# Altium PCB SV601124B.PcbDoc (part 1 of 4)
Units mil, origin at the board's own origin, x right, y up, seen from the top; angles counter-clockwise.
Board outline 3733 x 2734 mil, 4 copper layers (Top Layer, Mid-Layer 1, Mid-Layer 2, Bottom Layer), stack 60.2 mil thick; 246 components, 169 nets, 780 pads, 426 vias.
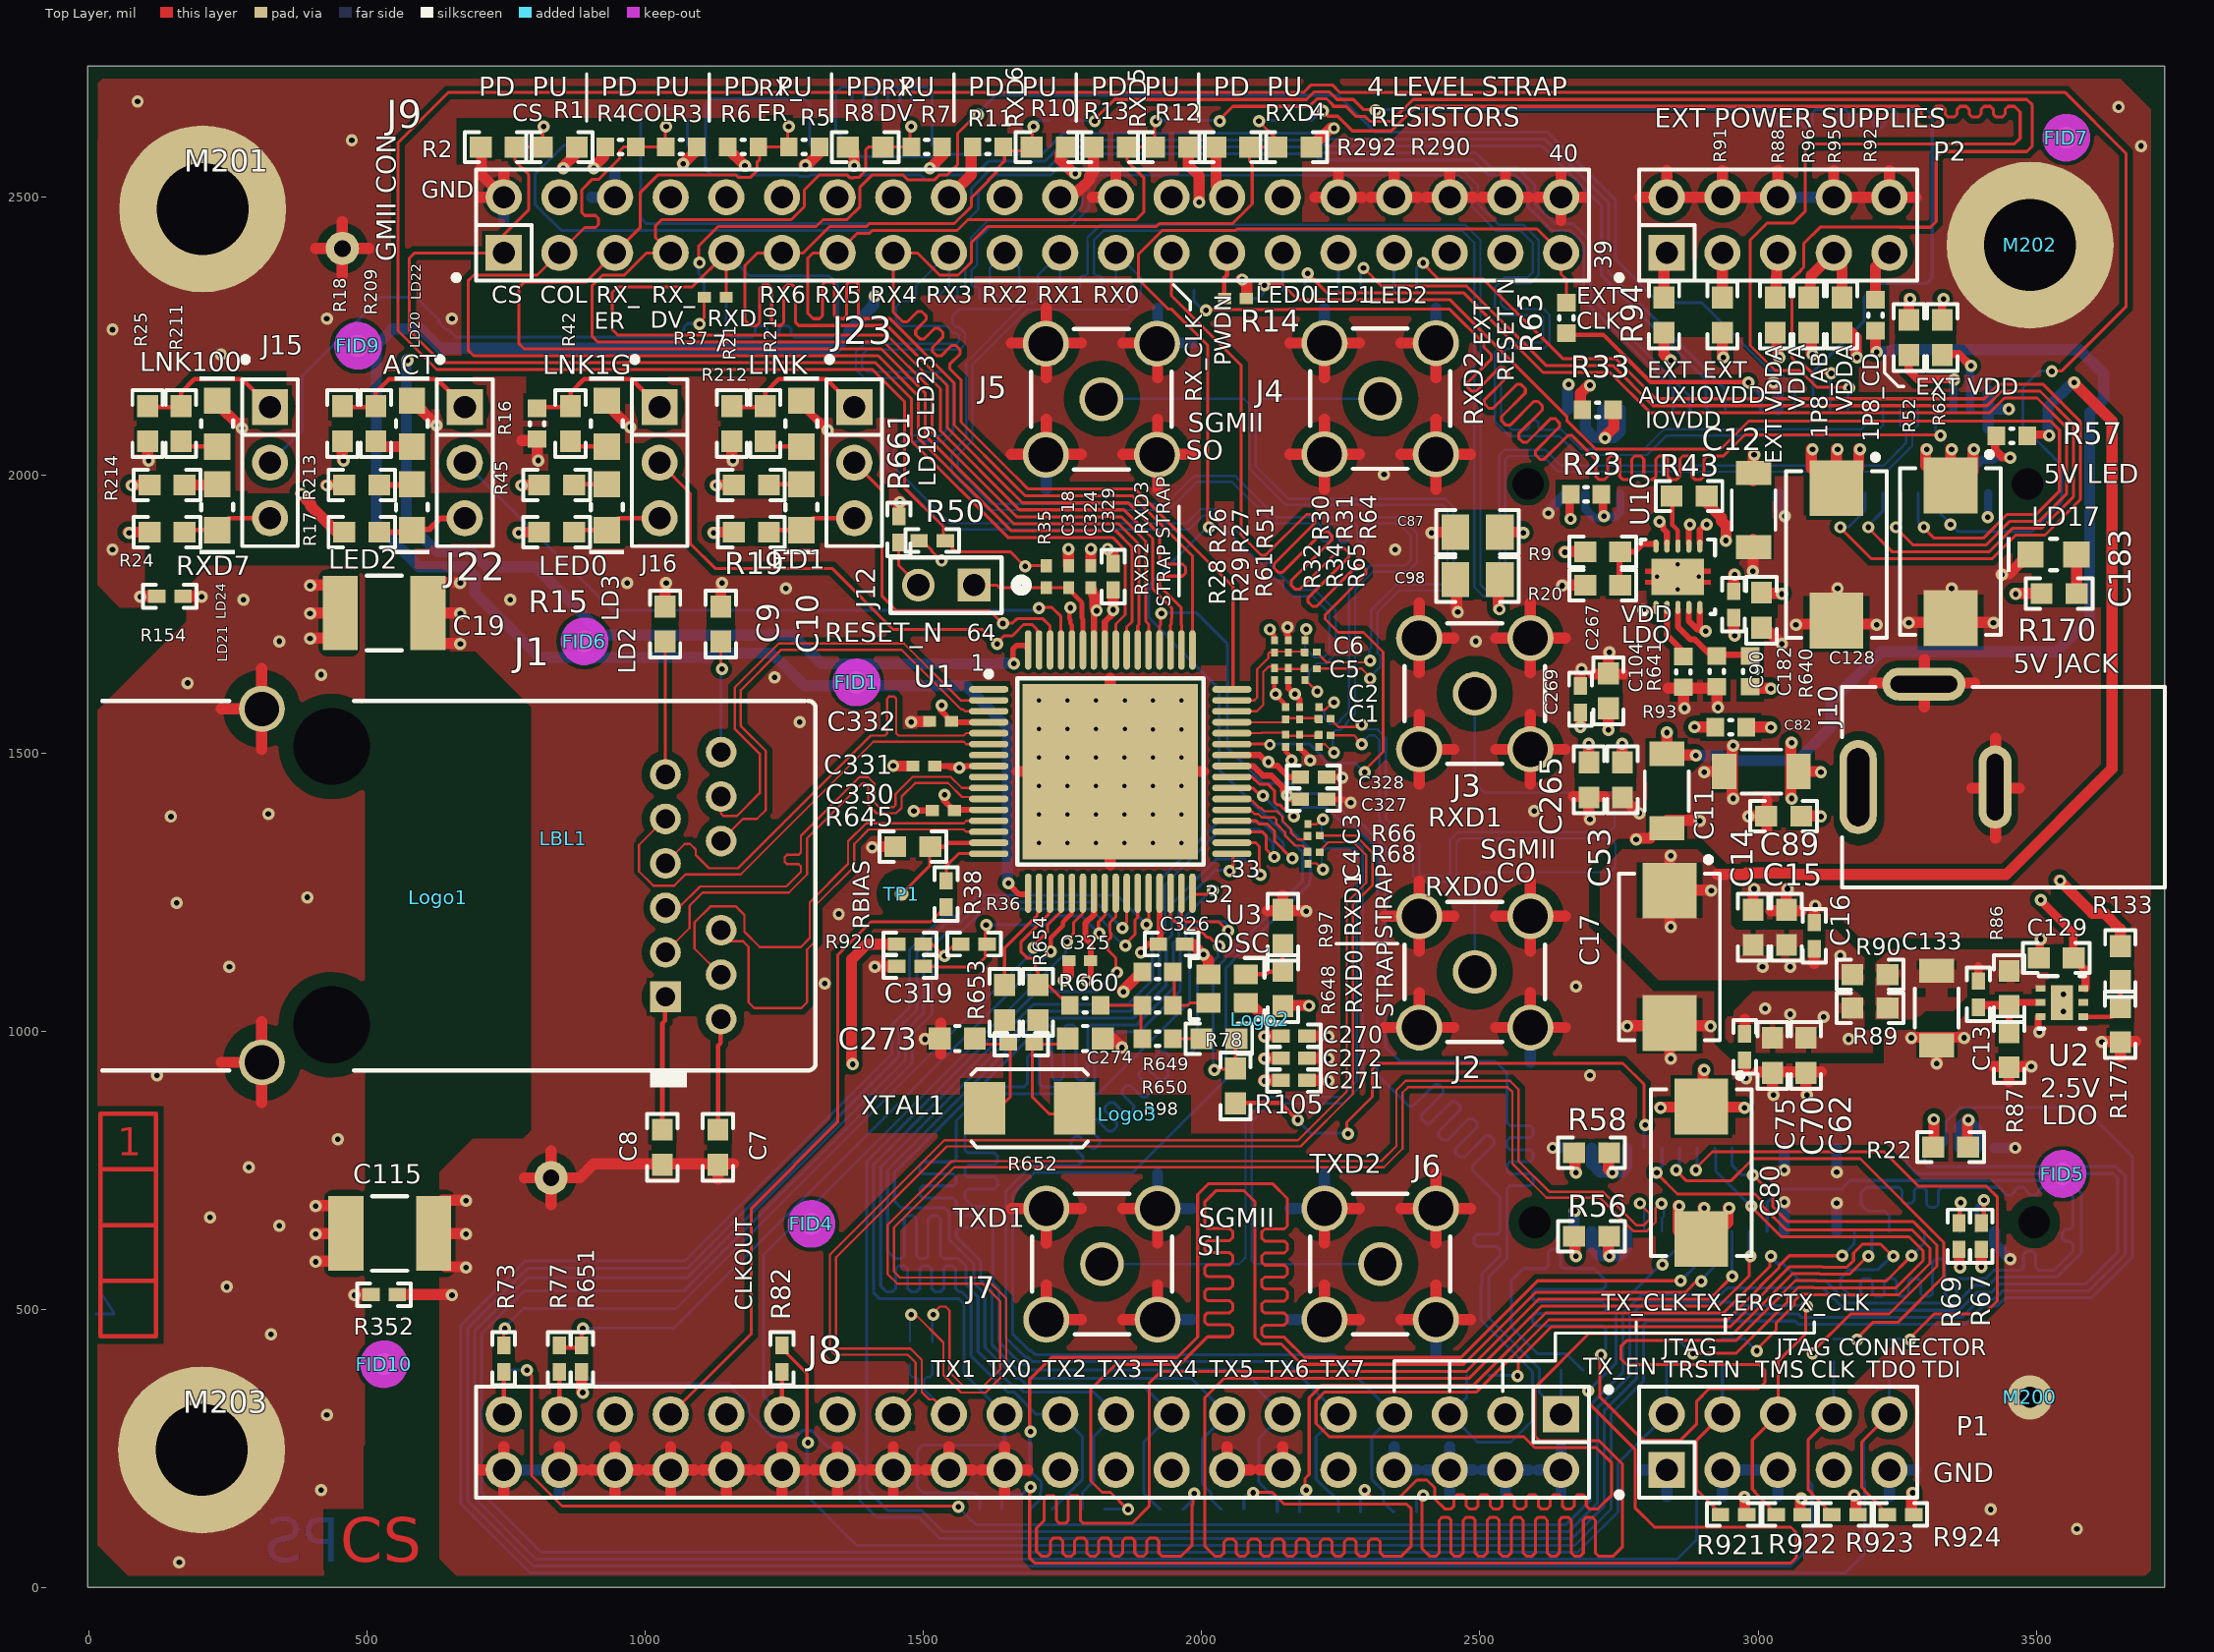
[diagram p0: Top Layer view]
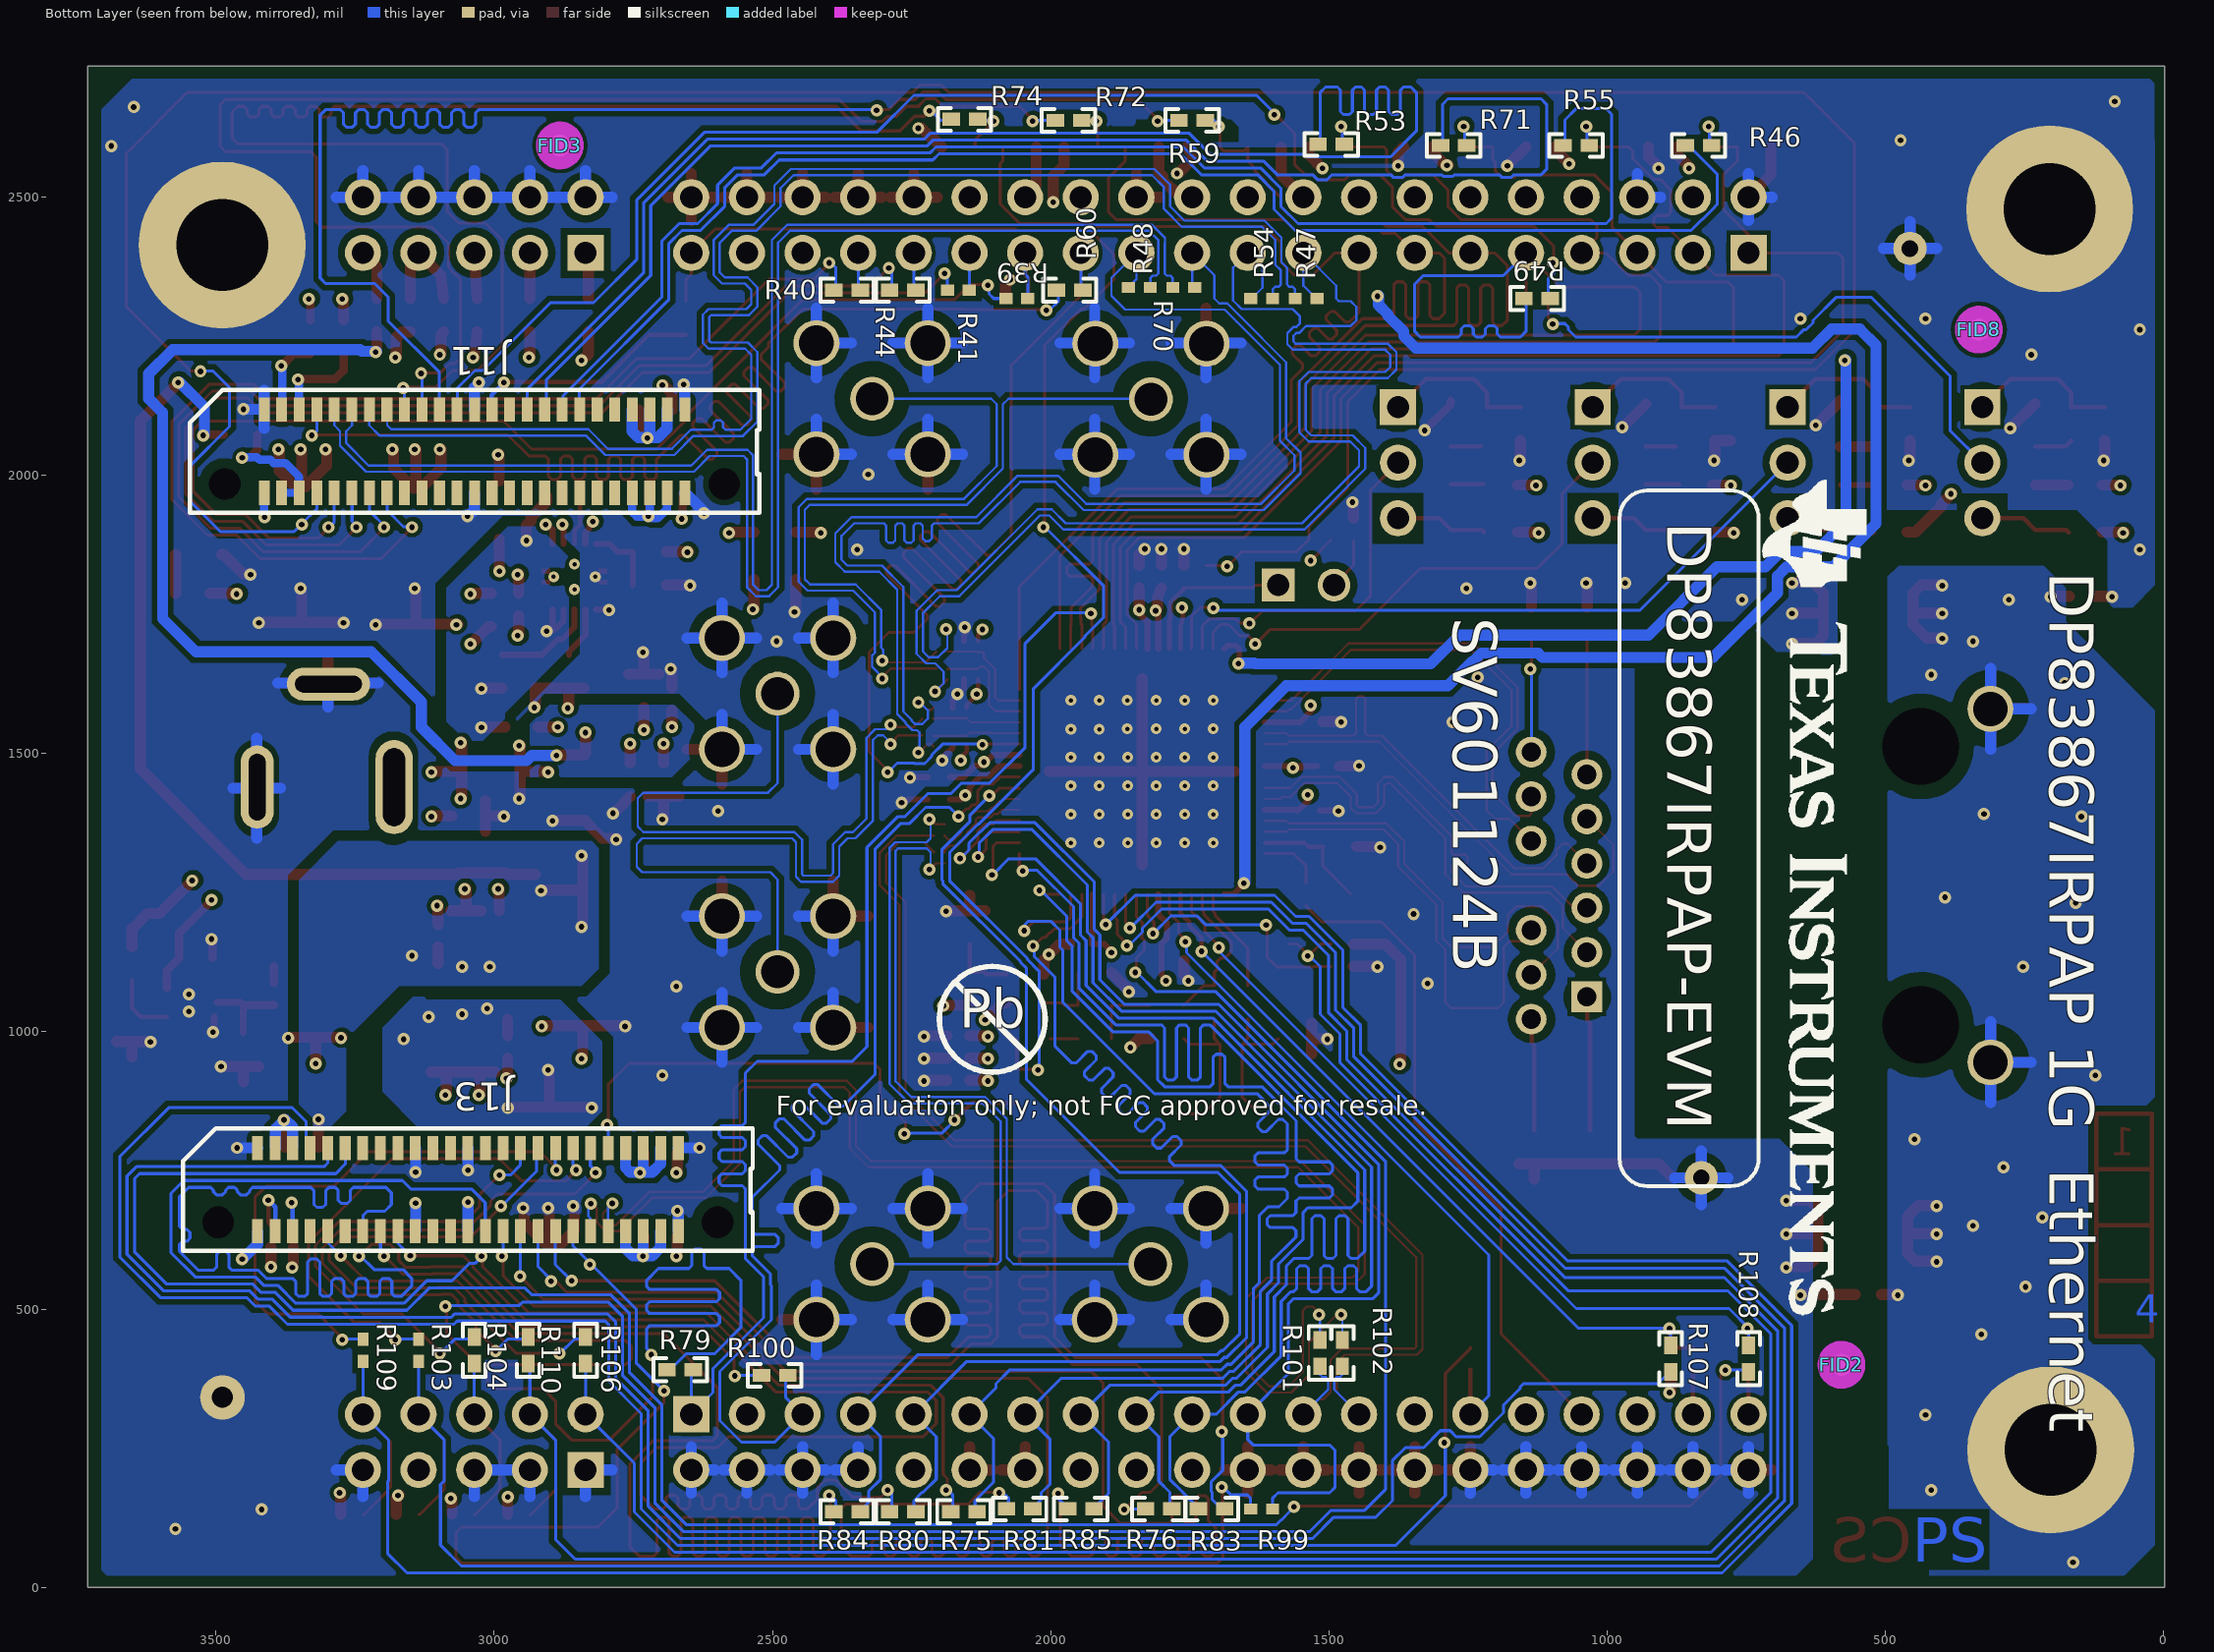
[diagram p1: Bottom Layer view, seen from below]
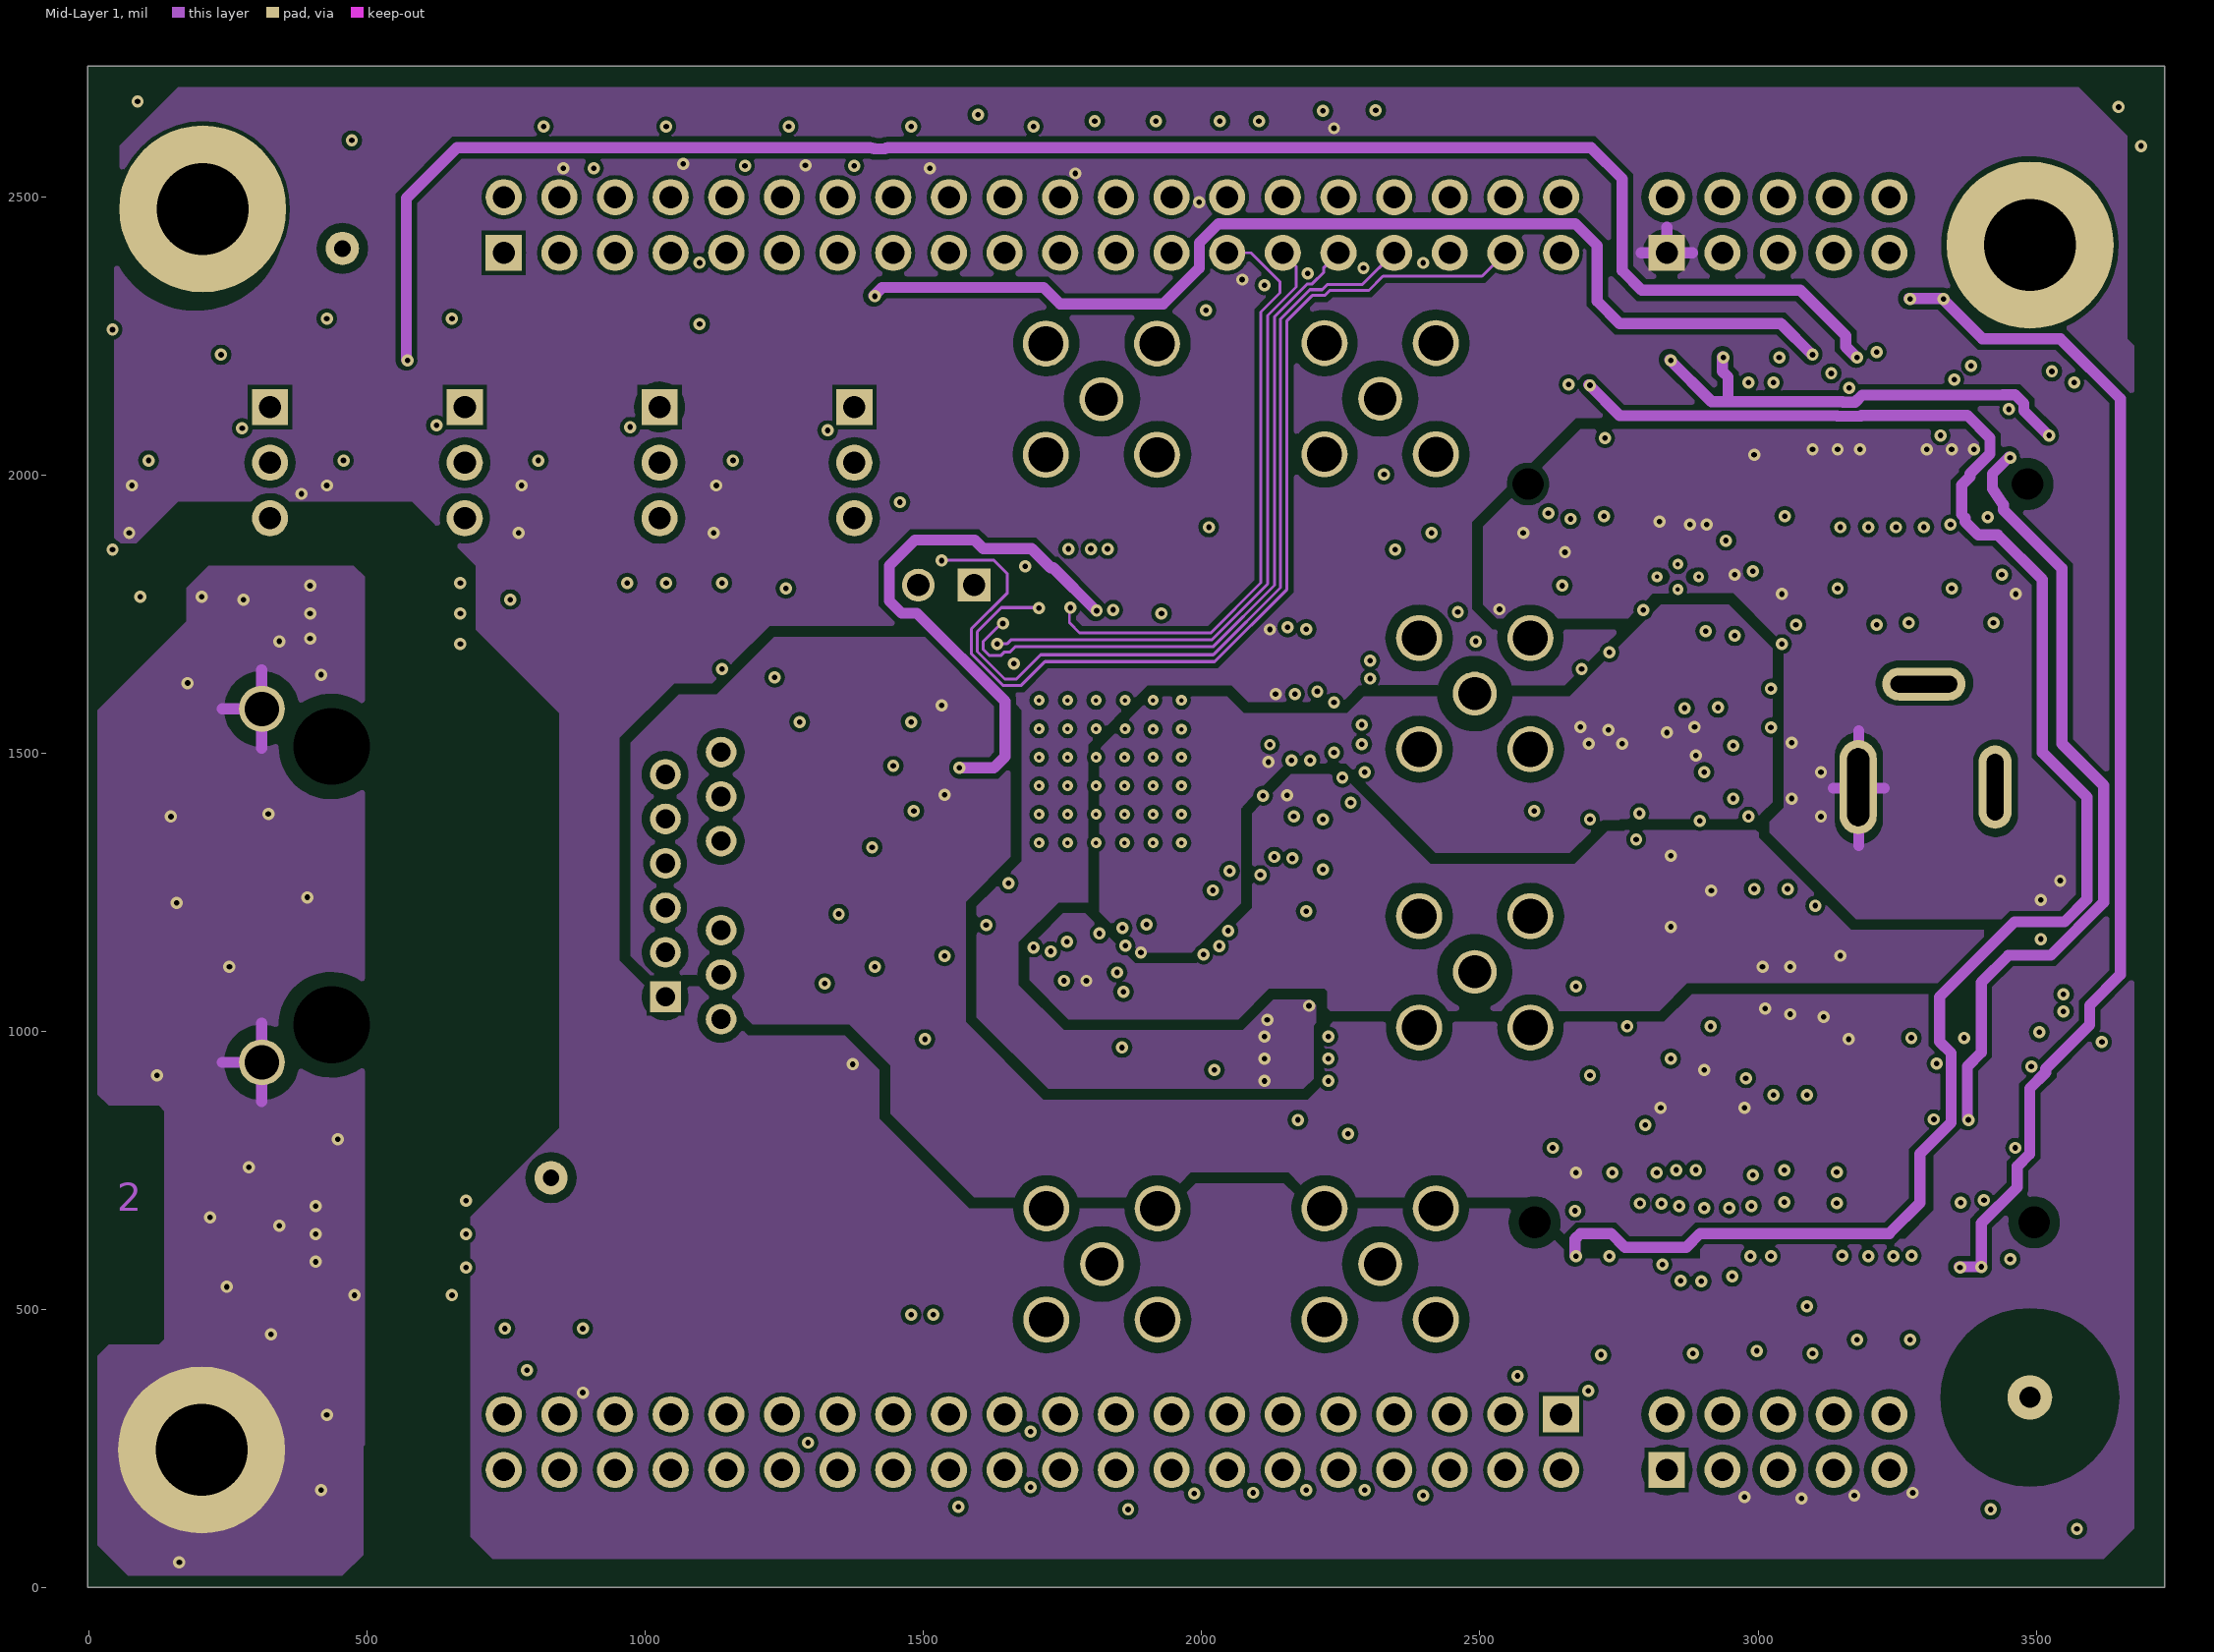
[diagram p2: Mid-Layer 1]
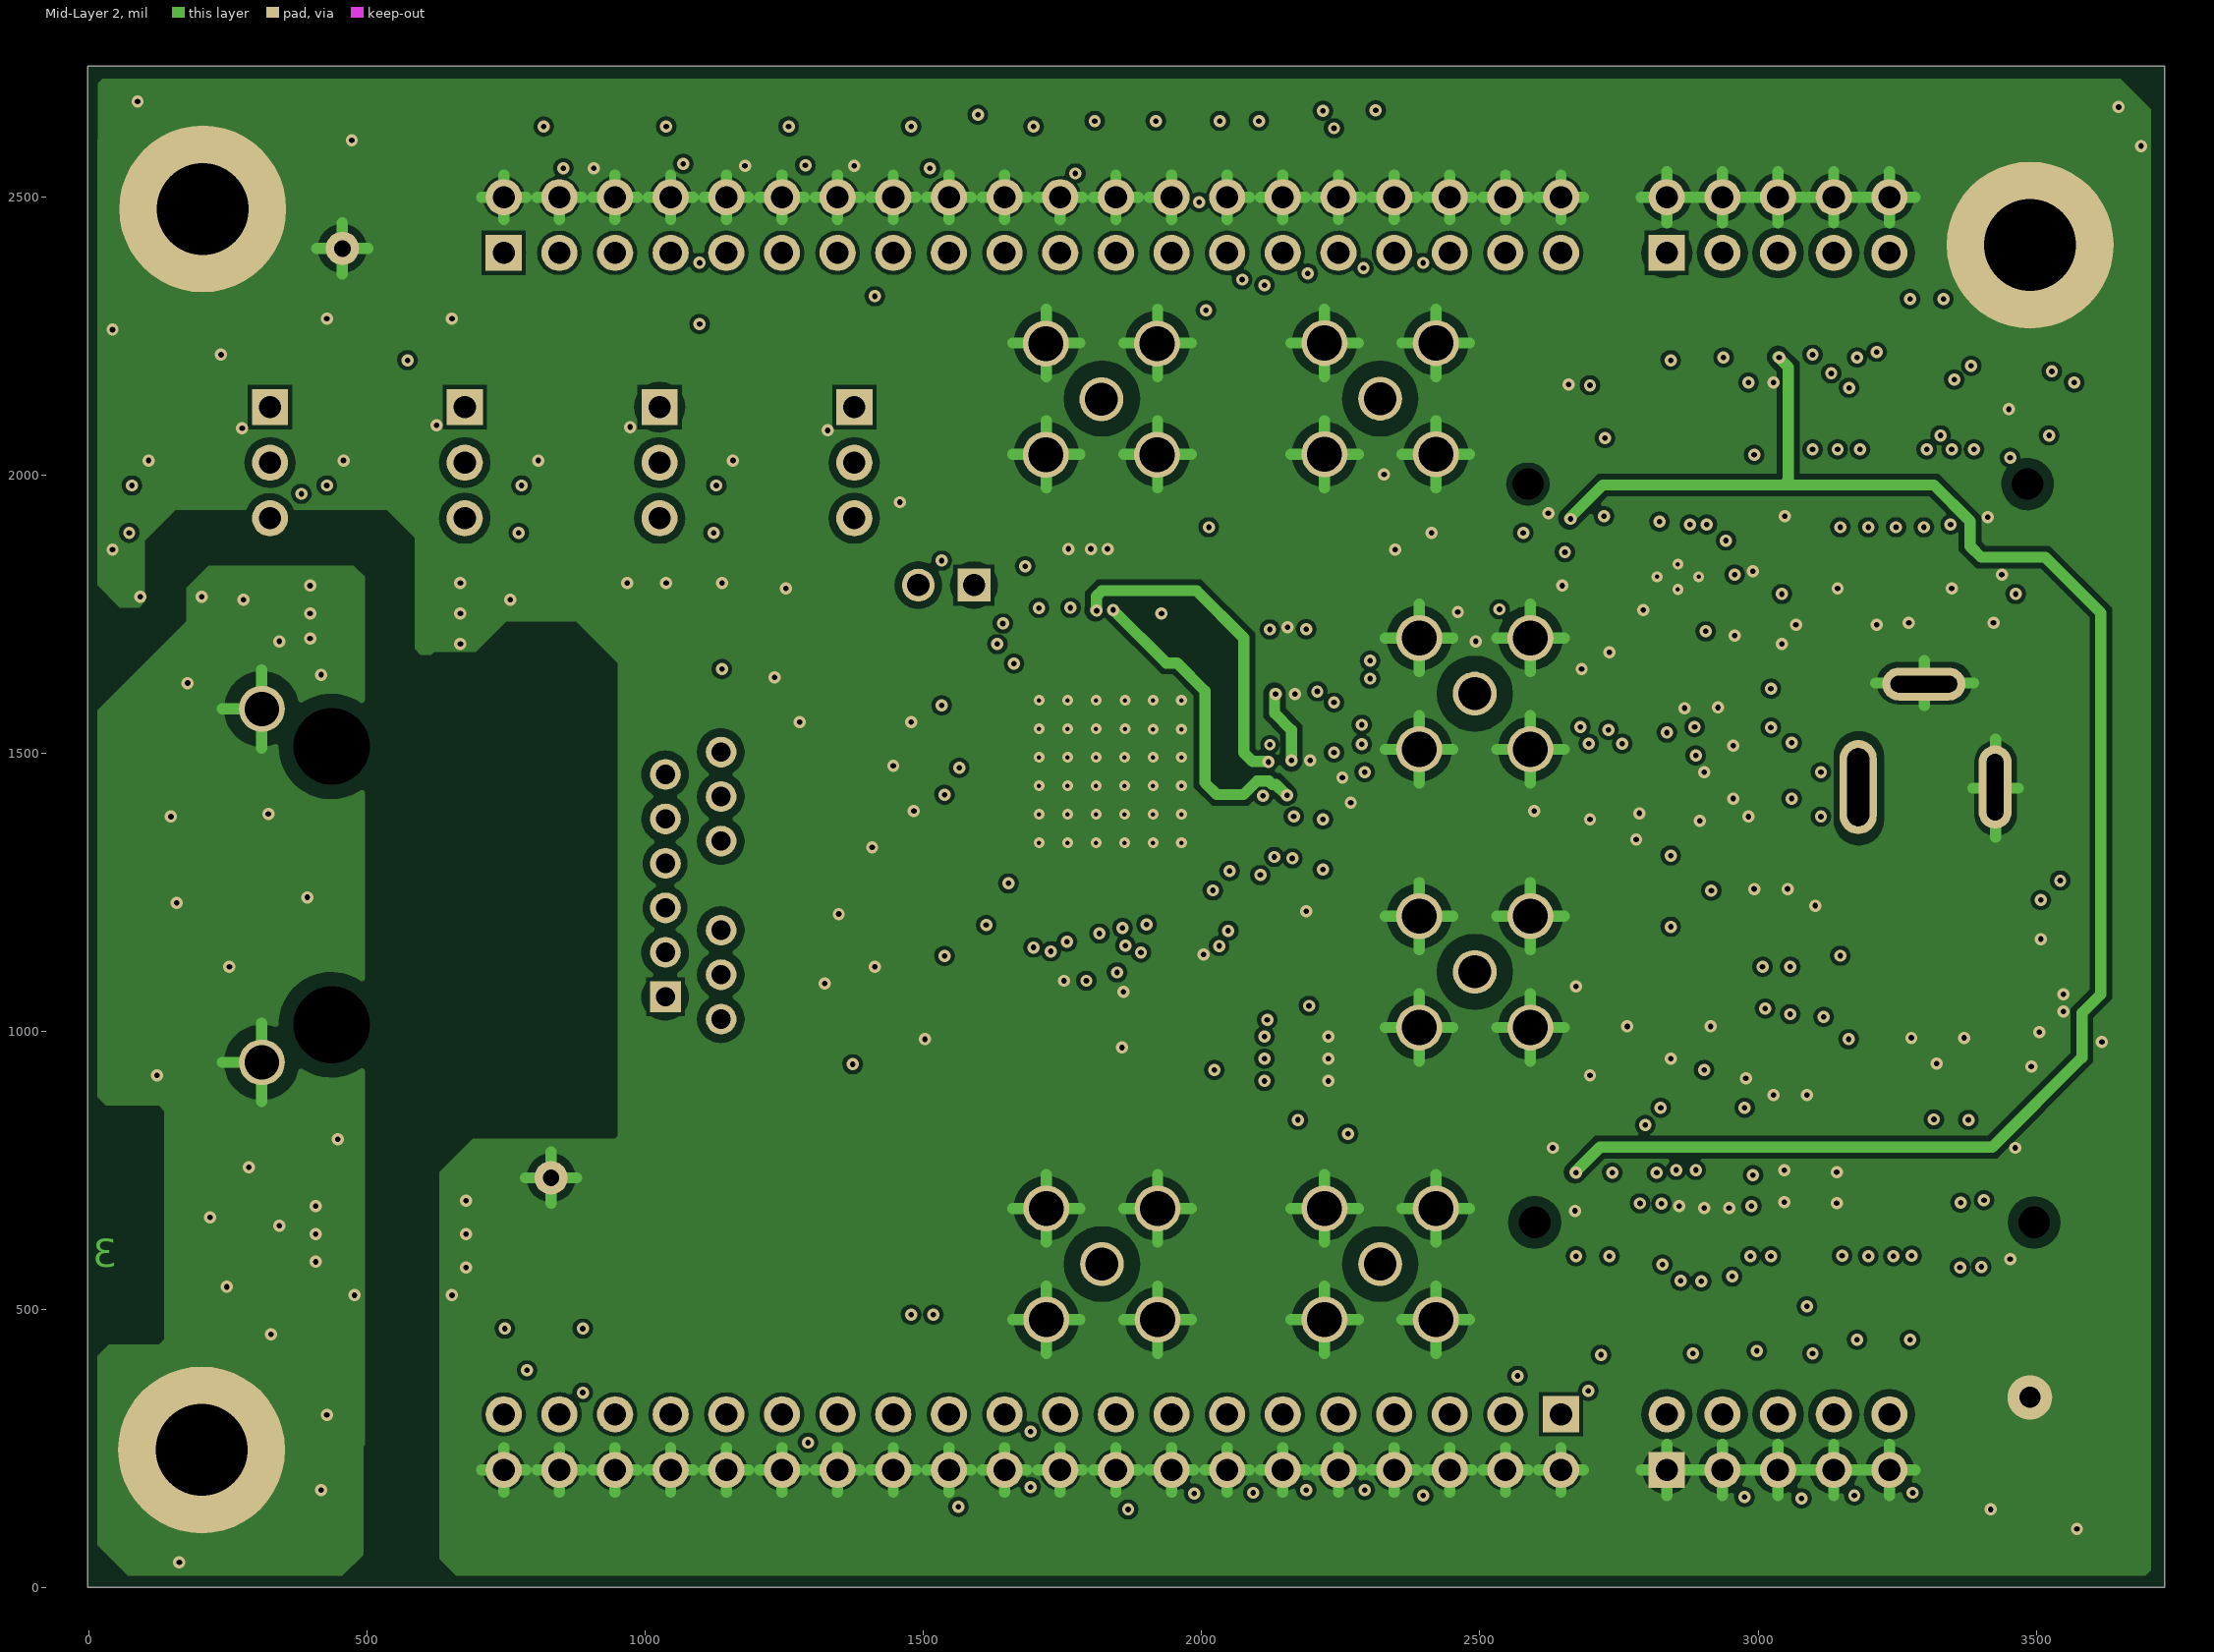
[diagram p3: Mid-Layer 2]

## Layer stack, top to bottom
Top Solder: solder mask 0.4, Solder Resist, Dk 3.5
Top Layer: signal copper 1.4
Dielectric1: core 3.5, FR-4, Dk 4.8
Mid-Layer 1: signal copper 1.4
Dielectric2: dielectric 47.6, FR-4, Dk 4.8
Mid-Layer 2: signal copper 1.4
Dielectric3: dielectric 3.5, FR-4, Dk 4.8
Bottom Layer: signal copper 1.4
Bottom Solder: solder mask 0.4, Solder Resist, Dk 3.5

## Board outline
-2,1 -2,2735 3731,2735 3731,1

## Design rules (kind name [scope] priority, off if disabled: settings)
AssemblyTestPointUsage [All] p1: valid=2
Clearance [All] p1: gap=7 except(5: Arc-Arc Track-THPad Arc-Track Track-Track Track-Via Arc-THPad)
ComponentClearance [All] p1: gap=0 collisioncheckmode=3 verticalgap=0 showdistances=FALSE
FabricationTestPointUsage [All] p1: valid=2 allowmultiple=FALSE
HoleSize [All] p1: absolutevalues=TRUE maxlimit=180 minlimit=1 maxpercent=80.000 minpercent=20.000
MinimumSolderMaskSliver [All] p1: minsoldermaskwidth=3.5
PlaneConnect [All] p1: planeconnectstyle=Direct reliefexpansion=20 reliefentries=4 reliefconductorwidth=10 reliefairgap=10
PolygonConnect [All] p1: connectstyle=Direct reliefconductorwidth=10 reliefentries=4 polygonreliefangle="90 Angle" airgapwidth=10
RoutingVias [All] p1: holewidth=12 width=23 viastyle="Through Hole" minholewidth=6 minwidth=12 maxholewidth=40 maxwidth=65
SilkToSilkClearance [All] p1: silktosilkclearance=0
SilkToSolderMaskClearance [IsPad] p1: minsilkscreentomaskgap=0 clearancetoexposedcopper=TRUE
SolderMaskExpansion [All] p1: expansion=0
UnpouredPolygon [All] p1: allowunpoured=FALSE
Width [All] p1: maxlimit=100 minlimit=4 preferedwidth=5.4
21 further rules are at their usual default settings.

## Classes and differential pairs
component class SV601124_Magnetics: LBL1 Logo1 Logo2 Logo3
component class Logo: Logo1
component class FiducialMark: FID1 FID2 FID3 FID4 FID5 FID6 FID7 FID8 FID9 FID10
component class Label: LBL1

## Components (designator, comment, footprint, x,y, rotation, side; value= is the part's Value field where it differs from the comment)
C1 "C0603X5R0J104K030BC" 0201L 2221,1532 r180 top
C2 "C0603X5R0J104K030BC" 0201L 2221,1562 r180 top
C3 "C0603X5R0J104K030BC" 0201L 2191,1362 r270 top
C4 "C0603X5R0J104K030BC" 0201L 2191,1312 r90 top
C5 "C0603X5R0J104K030BC" 0201L 2196,1652 r180 top
C6 "C0603X5R0J104K030BC" 0201L 2196,1682 r180 top
C7 "CL10B104KO8NNNC" 0603 1131,792 r270 top
C8 "CL10B104KO8NNNC" 0603 1031,792 r270 top
C9 "CL10B104KO8NNNC" 0603 1036,1732 r90 top
C10 "CL10B104KO8NNNC" 0603 1136,1732 r90 top
C11 "C3216X7R1V106M160AC" 1206_190 2836,1432 r270 top
C12 "C3216X7R1V106M160AC" 1206_190 2992,1937 r90 top
C13 "C0402C102J3RACTU" 0402 3396,1067 r270 top
C14 "C0603C103J5RACTU" 0603 2991,1187 r270 top
C15 "06035A102KAT2A" 0603 3051,1187 r270 top
C16 "CC0402JRNPO9BN101" 0402 3101,1172 r270 top
C17 "593D107X0010D2TE3" 7343-31 2841,1133.95 r270 top
C19 "DNP" 1812_254 531,1752 r180 top
C53 "CL10B104KO8NNNC" 0603 2756,1452 r270 top
C62 "C0603C103J5RACTU" 0603 3086,957 r90 top
C70 "06035A102KAT2A" 0603 3026,957 r90 top
C75 "CC0402JRNPO9BN101" 0402 2976,972 r90 top
C80 "593D107X0010D2TE3" 7343-31 2898,746 r270 top
C82 "C3216X7R1V106M160AC" 1206_190 3006,1467 r180 top
C87 "0805YD105KAT2A" 0805_HV 2496,1897 r0 top
C89 "C0603C103J5RACTU" 0603 3046,1387 r0 top
C90 "C0603C103J5RACTU" 0603 3006,1757 r90 top
C98 "CC0805ZRY5V6BB475" 0805_HV 2496,1812 r180 top
C104 "CL10C270FB8NNNC" 0603L 2866,1646 r90 top
C115 "DNP" 1812_254 541,637 r180 top
C128 "593D107X0010D2TE3" 7343-31 3141,1857 r270 top
C129 "CL10B105KQ8NNNC" 0603 3536,1132 r0 top
C133 "C3216X7R1V106M160AC" 1206_190 3321,1042 r270 top
C182 "CC0402JRNPO9BN101" 0402 2956,1767 r90 top
C183 "T491D227K006AT" 7343-31 3346,1862 r270 top
C265 "C0603C103J5RACTU" 0603 2696,1452 r90 top
C267 "06035A102KAT2A" 0603 2731,1612 r270 top
C269 "CC0402JRNPO9BN101" 0402 2681,1597 r270 top
C270 "C0402C103J5RACTU" 0402 2166,992 r180 top
C271 "C0402C102J3RACTU" 0402 2166,912 r180 top
C272 "CC0402JRNPO9BN101" 0402 2166,952 r180 top
C273 "CL10C330FB8NNNC" 0603_950 1561,987 r180 top
C274 "CL10C330FB8NNNC" 0603_950 1791,987 r0 top
C318 "GRM155R71H103KA88D" 0402L 1761,1817 r270 top
C319 "GRM155R71H103KA88D" 0402 1476,1117 r0 top
C324 "C0402C102J3RACTU" 0402L 1801,1817 r270 top
C325 "C0402C102J3RACTU" 0402L 1781,1127 r0 top
C326 "C0402C102J3RACTU" 0402 1946,1157 r180 top
C327 "C0402C102J3RACTU" 0402 2201,1417 r180 top
C328 "C0402C102J3RACTU" 0402 2201,1457 r180 top
C329 "C0402C102J3RACTU" 0402 1841,1817 r270 top
C330 "C0402C102J3RACTU" 0402L 1536,1397 r0 top
C331 "C0402C102J3RACTU" 0402L 1501,1477 r0 top
C332 "C0402C102J3RACTU" 0402L 1531,1557 r0 top
FID1 "Fiducial" Fiducial10-20 1380,1627 r0 top
FID2 "Fiducial" Fiducial10-20 579,401 r0 bottom
FID3 "Fiducial" Fiducial10-20 2882,2592 r0 bottom
FID4 "Fiducial" Fiducial10-20 1299,654 r0 top
FID5 "Fiducial" Fiducial10-20 3547,744 r0 top
FID6 "Fiducial" Fiducial10-20 891,1701 r0 top
FID7 "Fiducial" Fiducial10-20 3554,2606 r0 top
FID8 "Fiducial" Fiducial10-20 332,2261 r0 bottom
FID9 "Fiducial" Fiducial10-20 484,2232 r0 top
FID10 "Fiducial" Fiducial10-20 531,402 r0 top
J1 "7499111000A" Wurth_7499111000A 674,1262 r90 top
J2 "5-1814832-1" TE_5-1814832-1 2491,1107 r0 top
J3 "5-1814832-1" TE_5-1814832-1 2491,1607 r0 top
J4 "5-1814832-1" TE_5-1814832-1 2321,2137 r0 top
J5 "5-1814832-1" TE_5-1814832-1 1820,2136 r0 top
J6 "5-1814832-1" TE_5-1814832-1 2321,582 r0 top
J7 "5-1814832-1" TE_5-1814832-1 1821,582 r0 top
J8 "TSW-120-07-G-D" TSW-120-07-G-D 1696,262 r180 top
J9 "TSW-120-07-G-D" TSW-120-07-G-D 1696,2449 r0 top
J10 "RAPC712X" CONN_RAPC712X 3721,1439 r0 top
J11 "ERM8-025-05.0-L-DV-K-TR" SAMTEC_ERM8-025-05_0-L-DV-K-TR 3035.55,2042.58 r180 bottom
J12 "5-146261-1" CONN_5-146261-1 1541,1802 r180 top
J13 "ERM8-025-05.0-L-DV-K-TR" SAMTEC_ERM8-025-05_0-L-DV-K-TR 3047.36,715.8 r180 bottom
J15 "TSW-103-07-G-S" TSW-103-07-G-S 326,2022 r270 top
J16 "TSW-103-07-G-S" TSW-103-07-G-S 1026,2022 r270 top
J22 "TSW-103-07-G-S" TSW-103-07-G-S 676,2022 r270 top
J23 "TSW-103-07-G-S" TSW-103-07-G-S 1376,2022 r270 top
LBL1 "Size: 1.25\" x 0.25\"" Label_1250x250 853,1347 r90 top
LD2 "QTLP630C4TR" QTLP630C_Green 931,1942 r270 top
LD3 "QTLP630C4TR" QTLP630C_Green 931,2092 r90 top
LD17 "QTLP630C4TR" QTLP630C_Green 3531,1857 r180 top
LD19 "QTLP630C4TR" QTLP630C_Green 1281,1942 r270 top
LD20 "QTLP630C4TR" QTLP630C_Green 581,1942 r270 top
LD21 "QTLP630C4TR" QTLP630C_Green 231,1942 r270 top
LD22 "QTLP630C4TR" QTLP630C_Green 581,2092 r90 top
LD23 "QTLP630C4TR" QTLP630C_Green 1281,2092 r90 top
LD24 "QTLP630C4TR" QTLP630C_Green 231,2092 r90 top
Logo1 "Texas Instruments" TI_Horizontal_Overlay_Medium 628,1241 r270 top
Logo2 "Pb-Free Symbol" Pb-Free_Overlay_Medium 2105.06,1021.88 r180 top
Logo3 "FCC disclaimer" FCC_disclaimer 1866.7,851.51 r180 top
M200 "TESTPOINT" TESTPOINT#1 3488.49,342.36 r0 top
M201 "TESTPOINT" TESTPOINT#2 205,2478 r0 top
M202 "TESTPOINT" TESTPOINT#2 3489,2413 r90 top
M203 "TESTPOINT" TESTPOINT#2 203,248 r90 top
P1 "TSW-105-07-G-D" TSW-105-07-G-D 3036,262 r0 top
P2 "TSW-105-07-G-D" TSW-105-07-G-D 3036,2449 r0 top
R1 "RC0603FR-0711KL" 0603 846,2589 r0 top
R2 "RC0603FR-072K49L" 0603 736,2589 r0 top
R3 "RC0603FR-0711KL" 0603L 1065,2589 r0 top
R4 "RC0603FR-072K49L" 0603L 956,2589 r0 top
R5 "RC0603FR-0711KL" 0603L 1286,2589 r0 top
R6 "RC0603FR-072K49L" 0603L 1176,2589 r0 top
R7 "RC0603FR-076K04L" 0603L 1506,2589 r0 top
R8 "RC0603FR-072K49L" 0603 1396,2589 r0 top
R9 "RC0603JR-070RL" 0603 2721,1862 r180 top
R10 "RC0603FR-0711KL" 0603 1726,2589 r0 top
R11 "RC0603FR-072K49L" 0603L 1616,2589 r0 top
R12 "RC0603FR-0711KL" 0603 1946,2589 r0 top
R13 "RC0603FR-072K49L" 0603 1836,2589 r0 top
R14 "CRCW04022K20JNED" 0402L 2061,2317 r0 top
R15 "RC0603FR-0711KL" 0603 841,1897 r180 top
R16 "RC0603FR-072K49L" 0603L 806,2092 r90 top
R17 "RC0603FR-0711KL" 0603 491,1897 r180 top
R18 "RC0603FR-072K49L" 0603 456,2092 r90 top
R19 "RC0603FR-0711KL" 0603 1191,1897 r180 top
R20 "RC0603JR-070RL" 0603 2721,1802 r0 top
R21 "RC0603FR-072K49L" 0603 1156,2092 r90 top
R22 "RC0603JR-070RL" 0603 3346,792 r0 top
R23 "RC0603JR-070RL" 0603L 2691,1965 r0 top
R24 "RC0603FR-0711KL" 0603 141,1897 r180 top
R25 "RC0603FR-072K49L" 0603 106,2092 r90 top
R26 "ERJ-1GE0R00C" 0201L 2131,1692 r90 top
R27 "ERJ-1GE0R00C" 0201L 2156,1692 r270 top
R28 "ERJ-1GE0R00C" 0201L 2131,1642 r270 top
R29 "ERJ-1GE0R00C" 0201L 2156,1642 r90 top
R30 "ERJ-1GE0R00C" 0201L 2151,1572 r90 top
R31 "ERJ-1GE0R00C" 0201L 2176,1572 r270 top
R32 "ERJ-1GE0R00C" 0201L 2151,1522 r270 top
R33 "RC0603JR-070RL" 0603L 2712,2117 r180 top
R34 "ERJ-1GE0R00C" 0201L 2176,1522 r90 top
R35 "CRCW04020000Z0ED" 0402L 1721,1817 r90 top
R36 "RC0402JR-070RL" 0402 1591,1157 r0 top
R37 "CRCW04020000Z0ED" 0402L 1126,2319 r180 top
R38 "CRCW04020000Z0ED" 0402 1541,1247 r90 top
R39 "CRCW04020000Z0ED" 0402L 2061,2317 r180 bottom
R40 "CRCW04020000Z0ED" 0402 2366,2332 r0 bottom
R41 "CRCW04020000Z0ED" 0402L 2166,2332 r0 bottom
R42 "RC0603FR-07470RL" 0603 866,2092 r270 top
R43 "RC0603FR-0710KL" 0603 2876,1962 r180 top
R44 "CRCW04020000Z0ED" 0402 2266,2332 r0 bottom
R45 "RC0603FR-07470RL" 0603 841,1982 r0 top
R46 "CRCW04020000Z0ED" 0402 836,2592 r0 bottom
R47 "CRCW04020000Z0ED" 0402L 1541,2317 r0 bottom
R48 "CRCW04020000Z0ED" 0402L 1841,2337 r180 bottom
R49 "CRCW04020000Z0ED" 0402 1126,2317 r180 bottom
R50 "CRCW04020000Z0ED" 0402 1516,1882 r0 top
R51 "ERJ-1GE0R00C" 0201L 2186,1692 r90 top
R52 "RC0603JR-070RL" 0603 3271,2247 r90 top
R53 "CRCW04020000Z0ED" 0402 1496,2594 r180 bottom
R54 "CRCW04020000Z0ED" 0402L 1621,2317 r180 bottom
R55 "CRCW04020000Z0ED" 0402 1056,2592 r0 bottom
R56 "RC0603JR-070RL" 0603 2701,632 r0 top
R57 "RC0603JR-070RL" 0603L 3456,2070 r0 top
R58 "RC0603JR-070RL" 0603 2701,782 r180 top
R59 "CRCW04020000Z0ED" 0402 1746,2637 r0 bottom
R60 "CRCW04020000Z0ED" 0402 1966,2332 r0 bottom
R61 "ERJ-1GE0R00C" 0201L 2186,1642 r270 top
R62 "RC0603JR-070RL" 0603 3331,2247 r90 top
R63 "RC0603JR-070RL" 0603L 2656,2282 r90 top
R64 "ERJ-1GE0R00C" 0201L 2211,1572 r90 top
R65 "ERJ-1GE0R00C" 0201L 2211,1522 r270 top
R66 "ERJ-1GE0R00C" 0201L 2201,1352 r0 top
R67 "CRCW04020000Z0ED" 0402 3401,632 r90 top
R68 "ERJ-1GE0R00C" 0201L 2201,1322 r0 top
R69 "CRCW04020000Z0ED" 0402 3361,632 r90 top
R70 "CRCW04020000Z0ED" 0402L 1761,2337 r180 bottom
R71 "CRCW04020000Z0ED" 0402 1276,2592 r180 bottom
R72 "CRCW04020000Z0ED" 0402 1968,2637 r180 bottom
R73 "CRCW04020000Z0ED" 0402 746,412 r270 top
R74 "CRCW04020000Z0ED" 0402 2155,2639 r180 bottom
R75 "CRCW04020000Z0ED" 0402 2156,137 r0 bottom
R76 "CRCW04020000Z0ED" 0402 1806,142 r0 bottom
R77 "CRCW04020000Z0ED" 0402 846,412 r270 top
R78 "RC0603JR-070RL" 0603 2031,987 r0 top
R79 "CRCW04020000Z0ED" 0402 2666,392 r0 bottom
R80 "CRCW04020000Z0ED" 0402 2266,137 r0 bottom
R81 "CRCW04020000Z0ED" 0402 2056,142 r0 bottom
R82 "CRCW04020000Z0ED" 0402 1246,412 r270 top
R83 "CRCW04020000Z0ED" 0402 1711,142 r180 bottom
R84 "CRCW04020000Z0ED" 0402 2366,137 r0 bottom
R85 "CRCW04020000Z0ED" 0402 1946,142 r0 bottom
R86 "RC0603FR-0756K2L" 0603 3451,1077 r90 top
R87 "RC0603FR-0745K3L" 0603 3451,967 r90 top
R88 "RC0603JR-070RL" 0603 3031,2287 r90 top
R89 "RC0603JR-070RL" 0603 3201,1042 r180 top
R90 "RC0603JR-070RL" 0603 3201,1102 r0 top
R91 "RC0603JR-070RL" 0603 2936,2287 r270 top
R92 "RC0603JR-070RL" 0603L 3211,2287 r90 top
R93 "RC0603JR-070RL" 0603L 2951,1547 r180 top
R94 "RC0603JR-070RL" 0603 2831,2287 r270 top
R95 "RC0603JR-070RL" 0603 3151,2287 r90 top
R96 "RC0603JR-070RL" 0603 3091,2287 r90 top
R97 "RC0603JR-070RL" 0603 2146,1187 r90 top
R98 "RC0603JR-070RL" 0603L 1921,987 r180 top
R99 "CRCW04020000Z0ED" 0402L 1621,142 r0 bottom
R100 "CRCW04020000Z0ED" 0402 2496,382 r0 bottom
R101 "CRCW04020000Z0ED" 0402 1516,422 r90 bottom
R102 "CRCW04020000Z0ED" 0402 1476,422 r90 bottom
R103 "CRCW04020000Z0ED" 0402L 3136,427 r270 bottom
R104 "CRCW04020000Z0ED" 0402 3036,427 r270 bottom
R105 "RC0603JR-070RL" 0603 2061,902 r90 top
R106 "CRCW04020000Z0ED" 0402 2836,427 r270 bottom
R107 "CRCW04020000Z0ED" 0402 886,412 r90 bottom
R108 "CRCW04020000Z0ED" 0402 746,412 r90 bottom
R109 "CRCW04020000Z0ED" 0402L 3236,427 r270 bottom
R110 "CRCW04020000Z0ED" 0402 2939,427 r270 bottom
R133 "RC0603JR-070RL" 0603 3651,1122 r270 top
R154 "DNP" 0402 146,1782 r180 top
R170 "RC0603JR-07750RL" 0603 3541,1787 r180 top
R177 "RC0603JR-070RL" 0603 3651,1012 r90 top
R209 "RC0603FR-07470RL" 0603 516,2092 r270 top
R210 "RC0603FR-07470RL" 0603 1216,2092 r270 top
R211 "RC0603FR-07470RL" 0603 166,2092 r270 top
R212 "RC0603FR-07470RL" 0603 1191,1982 r0 top
R213 "RC0603FR-07470RL" 0603 491,1982 r0 top
R214 "RC0603FR-07470RL" 0603 141,1982 r180 top
R290 "RC0603FR-0711KL" 0603 2166,2589 r0 top
R292 "RC0603FR-072K49L" 0603 2056,2589 r0 top
R352 "DNP" 0402 531,527 r0 top
R640 "RC0603FR-071K87L" 0603L 2986,1647 r270 top
R641 "CPF0603B4K99E" 0603L 2926,1647 r90 top
R645 "RC0603JR-0710KL" 0603 1481,1332 r0 top
R648 "RC0603JR-070RL" 0603 2146,1077 r90 top
R649 "CRCW06034K70JNEA" 0603L 1921,1107 r0 top
R650 "RC0603JR-070RL" 0603L 1921,1047 r0 top
R651 "CRCW04022K20JNED" 0402 886,412 r90 top
R652 "RC0402FR-071ML" 0402 1676,977 r0 top
R653 "RC0603JR-070RL" 0603 1646,1052 r90 top
R654 "RC0603JR-070RL" 0603 1706,1052 r90 top
R660 "RC0603JR-070RL" 0603L 1791,1047 r0 top
R661 "CRCW04022K20JNED" 0402 1456,1902 r270 top
R920 "CRCW04022K20JNED" 0402 1476,1157 r0 top
R921 "CRCW04022K20JNED" 0402 2956,132 r180 top
R922 "CRCW04022K20JNED" 0402 3056,132 r180 top
R923 "CRCW04022K20JNED" 0402 3156,132 r180 top
R924 "CRCW04022K20JNED" 0402 3256,132 r180 top
TP1 "RBIAS" TP_25MIL-SMT 1461,1247 r90 top
U1 "DP83867PAP" PAP0064M_N 1836,1467 r0 top
U2 "TPS73501DRVR" DRV0006A 3546,1052 r0 top
U3 "SG-210STF25.000000MHZY" Epson_SG-210 2046,1077 r270 top
U10 "TPS74701DRCR" DRC0010A 2856,1817 r270 top
XTAL1 "ABM3-25.000MHZ-D2W-T" XTAL_ABM3 1691,862 r180 top

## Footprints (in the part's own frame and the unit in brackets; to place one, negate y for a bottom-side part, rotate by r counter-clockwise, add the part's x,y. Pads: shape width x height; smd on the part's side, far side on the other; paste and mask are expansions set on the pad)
0201L [mm] "Data from Kemet datasheet CC101_COM dated 7/28/11"
  rect 0.36x0.32 smd mask+0.048: 1(-0.28,0) 2(0.28,0)
  body extent -0.31,-0.16 0.31,0.16, height 0.26
0402 [mm] "0402 from SM-752 data"
  rect 0.8x0.6 smd: 1(-0.6,0) 2(0.6,0)
  silkscreen extent -1.22,-0.52 1.22,0.52, body extent -0.55,-0.3 0.55,0.3, height 0.6
0402L [mm] "0402 from SM-752 data"
  rect 0.6x0.5 smd: 1(-0.5,0) 2(0.5,0)
  body extent -0.55,-0.3 0.55,0.3, height 0.6
0603 [mm] "0603 from SM-752 data"
  rect 1x0.95 smd: 1(-0.8,0) 2(0.8,0)
  silkscreen extent -1.52,-0.69 1.52,0.69, body extent -0.87,-0.47 0.87,0.47, height 0.85
0603_950 [mm] "0603_950"
  rect 1x1 smd: 1(-0.8,0) 2(0.8,0)
  silkscreen extent -0.1,-0.58 0.1,0.58, body extent -0.87,-0.48 0.87,0.48, height 0.95
0603L [mm] "0603 from SM-752 data"
  rect 0.8x0.85 smd: 1(-0.7,0) 2(0.7,0)
  silkscreen extent -0.07,-0.33 0.07,0.33, body extent -0.87,-0.47 0.87,0.47, height 0.85
0805_HV [mil] "0805 with 30mil clearance between pads"
  rect 50x63 smd: 1(-40,0) 2(40,0)
  silkscreen extent -74,-40 74,40, body extent -43,-29 43,29, height 43
1206_190 [mm] "1206_190"
  rect 1.1x1.6 smd: 1(-1.7,0) 2(1.7,0)
  silkscreen extent -0.9,-1 0.9,1, body extent -1.75,-0.95 1.75,0.95, height 1.9
1812_254 [mm] "SMD, 2-Leads, Body 4.8x3.4mm"
  rect 1.6x3.4 smd: 1(-2,0) 2(2,0)
  silkscreen extent -0.8,-1.7 0.8,1.7, body extent -2.4,-1.7 2.4,1.7, height 2.54
7343-31 [mm] "Medium Density based on Kemet T495 dimensions"
  rect 2.55x2.45 smd: 1(-3.025,0) 2(3.025,0)
  silkscreen extent -4.56,-2.3 3.8,2.3, body extent -3.8,-2.3 3.8,2.3, height 3.1
CONN_5-146261-1 [mm] "Sullins"
  rect 1.5x1.5 hole 1.02: 1(-1.27,0)
  round 1.5 hole 1.02: 2(1.27,0)
  silkscreen extent -3.68,-1.27 2.54,1.27, body extent -2.51,-1.27 2.51,1.27, height 10.87
CONN_RAPC712X [mm] "Conn_DC Jack"
  oval 1.7x4.3 hole 1.01 slot 3.56 at 90 deg: 1(-13.741,0)
  oval 1.5x3.8 hole 0.76 slot 3.05 at 90 deg: 2(-7.493,0)
  oval 3.8x1.5 hole 0.76 slot 3.05 at 0 deg: 3(-10.744,4.7)
  silkscreen extent -14.48,-4.57 0.25,4.57, body extent -14.5,-4.57 0.23,4.83, height 11.18
DRC0010A [mm] "SON, 10-Leads, Body 3x3mm, Pitch 0.5mm, Thermal Pad 2.4x1.65mm, TI Recommended"
  oval 0.6x0.24 smd: 1(-1.4,1) 2(-1.4,0.5) 3(-1.4,0) 4(-1.4,-0.5) 5(-1.4,-1) 6(1.4,-1) 7(1.4,-0.5) 8(1.4,0) 9(1.4,0.5) 10(1.4,1)
  rect 1.65x2.4 smd paste-0.825: 11(0,0)
  Top Layer region: 0.135,-1.5 0.365,-1.5 0.365,-1.1 0.135,-1.1
  Top Layer region: -0.135,-1.1 -0.365,-1.1 -0.365,-1.5 -0.135,-1.5
  Top Layer region: -0.135,1.5 -0.365,1.5 -0.365,1.1 -0.135,1.1
  Top Layer region: 0.135,1.1 0.365,1.1 0.365,1.5 0.135,1.5
  silkscreen extent -1.7,-1.7 1.7,1.7, body extent -1.55,-1.55 1.55,1.55, height 1.01
DRV0006A [mm] "SON, 6-Leads, Body 2x2mm, Pitch 0.65mm, Thermal Pad 1.6x1mm, TI Recommended"
  rect 0.45x0.3 smd: 1(-0.975,0.65) 2(-0.975,0) 3(-0.975,-0.65) 4(0.975,-0.65) 5(0.975,0) 6(0.975,0.65)
  rect 1x1.6 smd paste-0.5: 7(0,0)
  silkscreen extent -1.05,-1.2 1.05,1.2, body extent -1.05,-1.05 1.05,1.05, height 0.81
Epson_SG-210 [mm] "SMD, 2-Leads, Body 2x2.5mm"
  rect 0.9x1.1 smd: 1(-0.65,0.85) 2(-0.65,-0.85) 3(0.65,-0.85) 4(0.65,0.85)
  silkscreen extent -1.4,-1.7 1.4,1.7, body extent -1.08,-1.33 1.08,1.33, height 0.91
FCC_disclaimer [mil]
Fiducial10-20 [mm]
  round 1 smd mask+0.5: 1(0,0)
  Top Layer keep-out circle w1.178: c0,0 r0.5
Label_1250x250 [mil] "Thermal Transfer Labels"
  round 1 on Mech14: 0(0,0)
  body extent -625,-125 625,125, height 1
PAP0064M_N [mm] "Thin QFP, 64-Leads, Body 10x10mm, Pitch 0.5mm, Thermal Pad 8x8mm, IPC Medium Density"
  oval 1.8x0.3 smd: 1(-5.55,3.75) 2(-5.55,3.25) 3(-5.55,2.75) 4(-5.55,2.25) 5(-5.55,1.75) 6(-5.55,1.25) 7(-5.55,0.75) 8(-5.55,0.25) 9(-5.55,-0.25) 10(-5.55,-0.75) 11(-5.55,-1.25) 12(-5.55,-1.75) 13(-5.55,-2.25) 14(-5.55,-2.75) 15(-5.55,-3.25) 16(-5.55,-3.75) 33(5.55,-3.75) 34(5.55,-3.25) 35(5.55,-2.75) 36(5.55,-2.25) 37(5.55,-1.75) 38(5.55,-1.25) 39(5.55,-0.75) 40(5.55,-0.25) 41(5.55,0.25) 42(5.55,0.75) 43(5.55,1.25) 44(5.55,1.75) 45(5.55,2.25) 46(5.55,2.75) 47(5.55,3.25) 48(5.55,3.75)
  oval 0.3x1.8 smd: 17(-3.75,-5.55) 18(-3.25,-5.55) 19(-2.75,-5.55) 20(-2.25,-5.55) 21(-1.75,-5.55) 22(-1.25,-5.55) 23(-0.75,-5.55) 24(-0.25,-5.55) 25(0.25,-5.55) 26(0.75,-5.55) 27(1.25,-5.55) 28(1.75,-5.55) 29(2.25,-5.55) 30(2.75,-5.55) 31(3.25,-5.55) 32(3.75,-5.55) 49(3.75,5.55) 50(3.25,5.55) 51(2.75,5.55) 52(2.25,5.55) 53(1.75,5.55) 54(1.25,5.55) 55(0.75,5.55) 56(0.25,5.55) 57(-0.25,5.55) 58(-0.75,5.55) 59(-1.25,5.55) 60(-1.75,5.55) 61(-2.25,5.55) 62(-2.75,5.55) 63(-3.25,5.55) 64(-3.75,5.55)
  rect 8x8 smd paste-1.78 mask-1.78: 65(0,0)
  silkscreen extent -5.67,-4.25 4.25,4.57, body extent -6,-6 6,6, height 1.12
Pb-Free_Overlay_Medium [mil]
QTLP630C_Green [mm] "SMT, 2-Leads, Body 2x1.25mm"
  rect 1.2x1.2 smd: 1(-1.05,0) 2(1.05,0)
  silkscreen extent -0.15,-0.8 2.15,0.8, body extent -1.1,-0.73 1.1,0.73, height 1.22
SAMTEC_ERM8-025-05_0-L-DV-K-TR [mm] "Samtec recommended footprint"
  rect 0.5x1.1 smd: 1(-9.6,1.9) 2(-9.6,-1.9) 3(-8.8,1.9) 4(-8.8,-1.9) 5(-8,1.9) 6(-8,-1.9) 7(-7.2,1.9) 8(-7.2,-1.9) 9(-6.4,1.9) 10(-6.4,-1.9) 11(-5.6,1.9) 12(-5.6,-1.9) 13(-4.8,1.9) 14(-4.8,-1.9) 15(-4,1.9) 16(-4,-1.9) 17(-3.2,1.9) 18(-3.2,-1.9) 19(-2.4,1.9) 20(-2.4,-1.9) 21(-1.6,1.9) 22(-1.6,-1.9) 23(-0.8,1.9) 24(-0.8,-1.9) 25(0,1.9) 26(0,-1.9) 27(0.8,1.9) 28(0.8,-1.9) 29(1.6,1.9) 30(1.6,-1.9) 31(2.4,1.9) 32(2.4,-1.9) 33(3.2,1.9) 34(3.2,-1.9) 35(4,1.9) 36(4,-1.9) 37(4.8,1.9) 38(4.8,-1.9) 39(5.6,1.9) 40(5.6,-1.9) 41(6.4,1.9) 42(6.4,-1.9) 43(7.2,1.9) 44(7.2,-1.9) 45(8,1.9) 46(8,-1.9) 47(8.8,1.9) 48(8.8,-1.9) 49(9.6,1.9) 50(9.6,-1.9)
  round 1 hole 1.45 unplated paste+0 mask+0.05: MH1(-11.4,-1.5) MH2(11.4,-1.5)
  silkscreen extent -13,-2.8 13,2.8, body extent -13,-2.8 13,2.8, height 8.9
TE_5-1814832-1 [mm] "SMA Straight PCB Socket Die Cast, TH"
  round 2 hole 1.5: 1(0,0)
  round 2.1 hole 1.6: 2(-2.54,2.54) 3(-2.54,-2.54) 4(2.54,-2.54) 5(2.54,2.54)
  silkscreen extent -3.2,-3.2 3.2,3.2, body extent -3.2,-3.2 3.2,3.2, height 9.5
TESTPOINT#1 [mil]
  round 80 hole 37.99: 1(0,0)
TESTPOINT#2 [mil]
  round 300 hole 165: 1(0,0)
TI_Horizontal_Overlay_Medium [mil]
TP_25MIL-SMT [mil]
  round 25 smd mask-2.5: 1(0,0)
TSW-103-07-G-S [mm] "Samtec 100mil, 1x3, 230 mil above insulator"
  rect 1.65x1.65 hole 1.016: 1(-2.54,0)
  round 1.65 hole 1.016: 2(0,0) 3(2.54,0)
  silkscreen extent -4.83,-1.27 3.81,1.27, body extent -3.81,-1.27 3.81,1.27, height 8.38
TSW-105-07-G-D [mm] "Samtec 100mil, 2x5, 230 mil above insulator"
  rect 1.65x1.65 hole 1.016 mask+0: 1(-5.08,-1.27)
  round 1.65 hole 1.016 mask+0: 2(-5.08,1.27) 3(-2.54,-1.27) 4(-2.54,1.27) 5(0,-1.27) 6(0,1.27) 7(2.54,-1.27) 8(2.54,1.27) 9(5.08,-1.27) 10(5.08,1.27)
  silkscreen extent -7.37,-2.54 6.35,2.54, body extent -6.35,-2.54 6.35,2.54, height 8.38
TSW-120-07-G-D [mm] "Samtec 100mil, 2x20, 230 mil above insulator"
  rect 1.65x1.65 hole 1.016 mask+0: 1(-24.13,-1.27)
  round 1.65 hole 1.016 mask+0: 2(-24.13,1.27) 3(-21.59,-1.27) 4(-21.59,1.27) 5(-19.05,-1.27) 6(-19.05,1.27) 7(-16.51,-1.27) 8(-16.51,1.27) 9(-13.97,-1.27) 10(-13.97,1.27) 11(-11.43,-1.27) 12(-11.43,1.27) 13(-8.89,-1.27) 14(-8.89,1.27) 15(-6.35,-1.27) 16(-6.35,1.27) 17(-3.81,-1.27) 18(-3.81,1.27) 19(-1.27,-1.27) 20(-1.27,1.27) 21(1.27,-1.27) 22(1.27,1.27) 23(3.81,-1.27) 24(3.81,1.27) 25(6.35,-1.27) 26(6.35,1.27) 27(8.89,-1.27) 28(8.89,1.27) 29(11.43,-1.27) 30(11.43,1.27) 31(13.97,-1.27) 32(13.97,1.27) 33(16.51,-1.27) 34(16.51,1.27) 35(19.05,-1.27) 36(19.05,1.27) 37(21.59,-1.27) 38(21.59,1.27) 39(24.13,-1.27) 40(24.13,1.27)
  silkscreen extent -26.43,-2.54 25.4,2.54, body extent -25.4,-2.54 25.4,2.54, height 8.38
Wurth_7499111000A [mm] "Modular Jack(Shielded), R/A, TH"
  rect 1.4x1.4 hole 0.89: 1(-5.075,-9.21)
  round 1.4 hole 0.89: 2(-3.045,-9.21) 3(-1.015,-9.21) 4(1.015,-9.21) 5(3.045,-9.21) 6(5.075,-9.21) 7(-6.095,-11.75) 8(-4.065,-11.75) 9(-2.035,-11.75) 10(2.035,-11.75) 11(4.065,-11.75) 12(6.095,-11.75)
  round 2.1 hole 1.57: 13(-8.065,9.21) 14(8.065,9.21)
  round 0 hole 3.5 unplated: MH1(-6.35,6.03) MH2(6.35,6.03)
  silkscreen extent -9.2,-16.06 8.44,16.5, body extent -10.74,-16.2 10.73,16.82, height 15.77
XTAL_ABM3 [mm] "Abracon recommended land pattern 12.28.10"
  rect 1.9x2.4 smd: 1(-2.05,0) 2(2.05,0)
  silkscreen extent -2.67,-1.78 2.67,1.78, body extent -2.6,-1.7 2.6,1.7, height 1.3

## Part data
C1 C2 C3 C4 C5 C6: "CAP, CERM, 0.1 µF, 6.3 V, +/- 10%, X5R, 0201"
C7 C8 C9 C10 C53: "CAP, CERM, 0.1 µF, 16 V, +/- 10%, X7R, 0603"
C11 C12 C82 C133: "CAP, CERM, 10 µF, 35 V, +/- 20%, X7R, 1206_190"
C13 C271 C324 C325 C326 C327 C328 C329 C330 C331 C332: "CAP, CERM, 1000 pF, 25 V, +/- 5%, X7R, 0402"
C14 C62 C89 C90 C265: "CAP, CERM, 0.01 µF, 50 V, +/- 5%, X7R, 0603"
C15 C70 C267: "CAP, CERM, 1000 pF, 50 V, +/- 10%, C0G/NP0, 0603"
C16 C75 C182 C269 C272: "CAP, CERM, 100 pF, 50 V, +/- 5%, C0G/NP0, 0402"
C17 C80 C128: "CAP, TA, 100 µF, 10 V, +/- 20%, 0.1 ohm, SMD"
C19 C115: library part 1812GC472KAT1A, "CAP, CERM, 4700 pF, 2000 V, +/- 10%, X7R, 1812"
C87: "CAP, CERM, 1 µF, 16 V, +/- 10%, X5R, 0805"
C98: "CAP, CERM, 4.7 µF, 10 V, +80/-20%, Y5V, 0805"
C104: "CAP, CERM, 27 pF, 50 V, +/- 1%, C0G/NP0, 0603"
C129: "CAP, CERM, 1 µF, 6.3 V, +/- 10%, X7R, 0603"
C183: "CAP, TA, 220 µF, 6.3 V, +/- 10%, 0.7 ohm, SMD"
C270: "CAP, CERM, 0.01 µF, 50 V, +/- 5%, X7R, 0402"
C273 C274: "CAP, CERM, 33 pF, 50 V, +/- 1%, C0G/NP0, 0603_950"
C318 C319: "CAP, CERM, 0.01 µF, 50 V, +/- 10%, X7R, 0402"
FID1 FID2 FID3 FID4 FID5 FID6 FID7 FID8 FID9 FID10: "Fiducial mark.  There is nothing to buy or mount."
J1: "RJ45, Gold, R/A, TH"
J2 J3 J4 J5 J6 J7: "SMA Straight PCB Socket Die Cast, 50 Ohm, TH"
J8 J9: "Header, 100mil, 20x2, Gold, TH"
J10: "Power Jack, mini, 2.5mm OD, R/A, TH"
J11 J13: "CONN MICRO HS TERM STRP HDR 50 POS"
J12: "Header, 100mil, 2x1, Gold, TH"
J15 J16 J22 J23: "Header, 100mil, 3x1, Gold, TH"
LBL1: library part THT-13-457-10, "Thermal Transfer Printable Labels, 1.250\" W x 0.250\" H - 10,000 per roll"
LD2 LD3 LD17 LD19 LD20 LD21 LD22 LD23 LD24: "LED, Green, SMD"
Logo1: library part TI_Logo, "Texas Instrument Corporate Signature"
Logo2: library part Pb-Free
Logo3: library part FCC_disclaimer, "FCC_disclaimer"
M200 M201 M202 M203: "TEST POINT.  No entry in BOM."
P1 P2: "Header, 100mil, 5x2, Gold, TH"
R1 R3 R5 R10 R12 R15 R17 R19 R24 R290: "RES, 11.0 k, 1%, 0.1 W, 0603"
R2 R4 R6 R8 R11 R13 R16 R18 R21 R25 R292: "RES, 2.49 k, 1%, 0.1 W, 0603"
R7: "RES, 6.04 k, 1%, 0.1 W, 0603"
R9 R20 R22 R23 R33 R52 R56 R57 R58 R62 R63 R78 R88 R89 R90 R91 R92 R93 R94 R95 R96 R97 R98 R105 R133 R177 R648 R650 R653 R654 R660: "RES, 0, 5%, 0.1 W, 0603"
R14 R651 R661 R920 R921 R922 R923 R924: "RES, 2.2 k, 5%, 0.063 W, 0402"
R26 R27 R28 R29 R30 R31 R32 R34 R51 R61 R64 R65 R66 R68: "RES, 0, 5%, 0.05 W, 0201"
R35 R36 R37 R38 R39 R40 R41 R44 R46 R47 R48 R49 R50 R53 R54 R55 R59 R60 R67 R69 R70 R71 R72 R73 R74 R75 R76 R77 R79 R80 R81 R82 R83 R84 R85 R99 R100 R101 R102 R103 R104 R106 R107 R108 R109 R110: "RES, 0, 5%, 0.063 W, 0402"
R42 R45 R209 R210 R211 R212 R213 R214: "RES, 470, 1%, 0.1 W, 0603"
R43: "RES, 10.0 k, 1%, 0.1 W, 0603"
R86: "RES, 56.2 k, 1%, 0.1 W, 0603"
R87: "RES, 45.3 k, 1%, 0.1 W, 0603"
R154 R352: library part RC0402FR-071ML, "RES, 1.00 M, 1%, 0.063 W, 0402"
R170: "RES, 750, 5%, 0.1 W, 0603"
R640: "RES, 1.87 k, 1%, 0.1 W, 0603"
R641: "RES, 4.99 k, 0.1%, 0.063 W, 0603"
R645: "RES, 10 k, 5%, 0.1 W, 0603"
R649: "RES, 4.7 k, 5%, 0.1 W, 0603"
R652: "RES, 1.00 M, 1%, 0.063 W, 0402"
TP1: library part TESTPOINT, "TEST POINT.  No entry in BOM."
U1: "Robust, Low Power 10/100/1000 Ethernet Physical Layer Transceiver, PAP0064M"
U2: "Single Output High PSRR LDO, 500 mA, Adjustable 1.25 to 6 V Output, 2.7 to 6.5 V Input, with Low IQ, 6-pin SON (DRV), -40 to 125 degC, Green (RoHS & no Sb/Br)"
U3: "OSC, 25 MHz, 1.6 to 3.6 V, SMD"
U10: "Single Output LDO, 500 mA, Adjustable 0.8 to 3.6 V Output, 0.8 to 5.5 V Input, with Programmable Soft Start, 10-pin SON (DRC), -40 to 125 degC, Green (RoHS & no Sb/Br)"
XTAL1: "Crystal, 25 MHz, 18 pF, SMD"

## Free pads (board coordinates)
  round 60 hole 30: 0(456,2407) 0(831,737)

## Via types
v1: diameter 22, hole 10, Top Layer to Bottom Layer, 385 vias
v2: diameter 19.68, hole 7.87, Top Layer to Bottom Layer, 40 vias
v3: diameter 20, hole 10, Top Layer to Bottom Layer, 1 vias

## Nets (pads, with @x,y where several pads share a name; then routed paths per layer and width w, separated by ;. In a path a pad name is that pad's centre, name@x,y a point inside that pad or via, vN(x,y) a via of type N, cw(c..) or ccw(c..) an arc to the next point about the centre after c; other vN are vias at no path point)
5V_SUPPLY: C12.2 C82.1 C87.2 C89.2 C90.2 C98.1 C128.1 C129.2 C182.2 C183.1 J10.1 R9.2 R133.1 R170.2 U2.6 U10.1 U10.2 U10.4 | length 1788.5
  Top Layer w11: v1@2821,1917 2829.5,1908.5 2829.5,1903.42 2836.31,1896.61 U10.4@2836.31,1876.06 ; U10.2@2875.69,1876.06 v1@2875.69,1911.69 ; U10.1@2895.37,1876.06 2895.37,1901.37 v1@2906,1912
  Top Layer w15: v1@3506,1237 3566,1177 3566,1132 3588.53,1109.47 U2.6@3588.53,1077.6
  Top Layer w20: v1@2533.48,1759.48 C98.1@2533.48,1812 ; C87.2@2533.48,1897 v1@2576,1897 ; v1@2651,1862 R9.2@2691,1862 ; C182.2@2956,1787 v1@2956,1822 ; C12.2@2991,1989.52 v1@2991,2037 ; C90.2@3006,1787 v1@3041,1787 ; v1@3058.52,1419.52 C82.1@3058.52,1467 ; v1@3058.52,1519.52 C82.1@3058.52,1467 ; C89.2@3076,1387 v1@3111,1387 ; v1@3096,2047 3096,2012 3131.99,1976.01 C128.1@3141,1976.01 ; v1@3111,1467 C82.1@3058.52,1467 ; v1@3141,2047 C128.1@3141,1976.01 ; v1@3181,2047 3181,2012 3145.01,1976.01 C128.1@3141,1976.01 ; v1@3301,2047 3301,2017 3338.99,1979.01 C183.1@3346,1979.01 ; v1@3346,2047 C183.1@3346,1979.01 ; v1@3386,2047 3386,2007 3358.01,1979.01 C183.1@3346,1979.01 ; v1@3461,1787 R170.2@3511,1787 ; v1@3541,1272 3601,1212 3623,1212 3651,1184 R133.1@3651,1152
  Mid-Layer 1 w20: 3135.48,1437 J10.1@3181,1437 ; 3181,1333.98 J10.1@3181,1437 ; 3181,1540.02 J10.1@3181,1437 ; 3226.52,1437 J10.1@3181,1437
  other v1: 3508,1236 3543,1271 3113,1386 3060.52,1418.52 3113,1466 3060.52,1518.52 2535.48,1758.48 3043,1786 3463,1786 2958,1821 2653,1861 2578,1896 2877.69,1910.69 2908,1911 2823,1916 2993,2036 3098,2046 3143,2046 3183,2046 3303,2046 3348,2046 3388,2046
25M_EXT: J9.39 R63.2 R78.2 R105.2 | length 2727.4
  Top Layer w5.4: v1@2011,1907 2011,2232.85 1946.15,2297.7 1940.3,2297.7 1886.23,2351.77 1886.23,2396.13 1929.33,2439.23 2060.77,2439.23 2063.54,2442 2603,2442 J9.39@2646,2399 2646,2360.76 2656,2350.76 R63.2@2656,2312 ; v1@2021,932 2061,932 R78.2@2061,987
  Bottom Layer w5.4: v1@2011,1907 1905.3,1801.3 1905.3,1743.42 1938.86,1709.86 1938.86,1708.14 2031,1616 2031,1471 2130,1372 2131,1372 2181.7,1321.3 2181.7,1270.7 2041.93,1130.93 2041.93,1129.39 2021,1108.46 v1@2021,932
  other v1: 2023,931 2013,1906
25M_REF: R649.2 R650.2 U3.3 | length 123.4
  Top Layer w5.4: R649.2@1951,1107 1951,1047 1975.7,1047 1980.19,1051.49 U3.3@2012.5,1051.49
ATP_16: R38.2 U1.16 | length 113.7
  Top Layer w5.4: R38.2@1541,1267 1541,1297 1563.4,1319.4 U1.16@1615.46,1319.4
AUX_IOVDD: C270.2 C271.2 C272.2 P2.1 R1.2 R3.2 R5.2 R7.2 R10.2 R12.2 R14.2 R15.2 R17.2 R19.2 R24.2 R26.2 R28.2 R30.2 R32.2 R45.1 R94.1 R212.1 R213.1 R214.2 R290.2 R648.1 R651.1 R920.1 R921.1 R922.1 R923.1 R924.1 U3.4 | length 1953.7
  Top Layer w8: v1@2121,1723.33 2121,1722 2131,1712 R26.2@2131,1701.3 ; R28.2@2131,1632.7 2131,1607 2151,1587 R30.2@2151,1581.3 ; R32.2@2151,1512.7 2151,1503.12 2161,1493.12 2161,1487.45 v1(2161.45,1487)
  Top Layer w20: v1@71,1897 R24.2@111,1897 ; v1@76,1982 R214.2@111,1982 ; v1@380.23,1967 399.33,1947.9 399.33,1943.67 446,1897 R17.2@461,1897 ; v1@426,1982 R213.1@461,1982 ; v1@771,1897 R15.2@811,1897 ; v1@776,1982 R45.1@811,1982 ; v1@851,2552 876,2577 R1.2@876,2589 ; v1@886,352 R651.1@886,392 ; v1@1066.59,2559.93 1068.93,2559.93 1096,2587 R3.2@1096,2589 ; v1@1121,1897 R19.2@1161,1897 ; v1@1126,1982 R212.1@1161,1982 ; v1@1286,2557 1291,2557 1316,2582 R5.2@1316,2589 ; v1@1371,942 1371,1129.13 1398.87,1157 R920.1@1456,1157 ; v1(1511.91,2551.09) 1536,2575.18 R7.2@1536,2589 ; R10.2@1756,2589 1756,2587 1746,2577 1746,2566.23 1769.54,2542.69 v1@1771.4,2542.69 ; R12.2@1976,2589 1976,2557 1995.78,2537.22 v1(1995.78,2490.28) ; v1@2071,2352 2081,2342 R14.2@2081,2317 ; U3.4@2079.5,1051.49 2086.51,1051.49 v1@2116,1022 ; v1@2111,912 C271.2@2146,912 ; v1@2111,952 C272.2@2146,952 ; v1@2111,992 C270.2@2146,992 ; R648.1@2146,1047 v1@2191,1047 ; R290.2@2196,2589 2211.9,2604.9 2213.9,2604.9 2232.9,2623.9 v1@2236,2623.9 ; R94.1@2831,2317 2831,2394 P2.1@2836,2399 ; v1@2973.56,164.56 2976,162.13 R921.1@2976,132 ; R922.1@3076,132 v1@3076,162 ; v1@3171.06,167.06 3176,162.13 R923.1@3176,132 ; R924.1@3276,132 v1@3276,172
  Mid-Layer 1 w20: 2789.98,2399 P2.1@2836,2399 ; 2836,2445.02 P2.1@2836,2399 ; 2882.02,2399 P2.1@2836,2399
  Mid-Layer 2 w20: v1@2131,1607 2131,1572 2161.45,1541.55 v1(2161.45,1487)
  other v1: 3078,161 2975.56,163.56 3173.06,166.06 3278,171 888,351 2113,911 1373,941 2113,951 2113,991 2118,1021 2193,1046 2133,1606 2123,1722.33 73,1896 773,1896 1123,1896 382.23,1966 78,1981 428,1981 778,1981 1128,1981 2073,2351 1773.4,2541.69 853,2551 1288,2556 1068.59,2558.93 2238,2622.9
CLKOUT: J8.29 R82.2 U1.22 | length 1265.9
  Top Layer w5.4: v1@1756,1162 1769.94,1175.94 1769.94,1195.77 1786.8,1212.63 U1.22@1786.8,1246.46
  Top Layer w8: J8.29@1246,312 R82.2@1246,392
  Bottom Layer w5.4: J8.29@1246,312 1212.9,345.1 1212.9,598.36 1756,1141.46 v1@1756,1162
  other v1: 1758,1161
COL: J9.3 R3.1 R4.2 R55.1 U1.55 | length 2319.7
  Top Layer w5.4: v1@1036,2627 1036,2589 961.3,2589 953.89,2581.59 953.89,2568.25 916.94,2531.3 905.3,2531.3 886.23,2512.23 886.23,2471.63 891.63,2466.23 910.77,2466.23 916.17,2460.83 916.17,2450.03 910.77,2444.63 891.63,2444.63 J9.3@846,2399 805.77,2358.77 692,2358.77 682,2348.77 682,2224.1 692,2214.1 1418.98,2214.1 1490.8,2142.28 1490.8,2066.58 1657.28,1900.1 1845.28,1900.1 1875.14,1870.24 1875.14,1736.22 1865.52,1726.6 U1.55@1865.52,1687.54
  Bottom Layer w5.4: R55.1@1036,2592 v1@1036,2627
  other v1: 1038,2626
COL_EMB: J11.35 R55.2 | length 2582.8
  Bottom Layer w5.4: R55.2@1076,2592 1076,2638 1056,2658 1002,2658 992,2648 992,2461.63 1002,2451.63 1555.53,2451.63 1586.23,2482.33 1586.23,2514.77 1623.09,2551.63 1724.19,2551.63 1761.96,2589.4 2206.14,2589.4 2217.14,2578.4 2493.14,2578.4 2519.91,2551.63 2567.81,2551.63 2598.63,2520.81 2598.63,2487.47 2634.47,2451.63 2667.81,2451.63 2698.63,2420.81 2698.63,2320.09 2876,2142.72 2876,2120.13 J11.35@2878.55,2117.58
CS: J9.1 R1.1 R2.2 R46.1 U1.56 | length 2324.4
  Top Layer w5.4: v1@816,2627 816,2589 766,2589 766,2564.3 791,2539.3 791,2477 746,2432 J9.1@746,2399 586,2399 576,2389 576,2260 634.3,2201.7 1413.84,2201.7 1478.4,2137.14 1478.4,2061.44 1652.14,1887.7 1840.14,1887.7 1862.74,1865.1 1862.74,1748.96 1845.84,1732.06 U1.56@1845.84,1687.54
  Bottom Layer w5.4: R46.1@816,2592 v1@816,2627
  other v1: 818,2626
CS_EMB: J11.37 R46.2 | length 2560.6
  Bottom Layer w5.4: R46.2@856,2592 854,2592 802,2540 802,2487 805.77,2483.23 805.77,2482.33 829.33,2458.77 830.23,2458.77 849.77,2439.23 1560.67,2439.23 1598.63,2477.19 1598.63,2509.63 1628.23,2539.23 1729.33,2539.23 1767.1,2577 2201,2577 2212,2566 2488,2566 2514.77,2539.23 2562.67,2539.23 2586.23,2515.67 2586.23,2482.33 2629.33,2439.23 2662.67,2439.23 2686.23,2415.67 2686.23,2314.95 2847.23,2153.95 2847.23,2118.26 J11.37@2846.55,2117.58
DM_A: J1.10 U1.3 | length 857.4
  Top Layer w4.1: J1.10@1136,1342 1175.82,1381.82 1201,1381.82 1217.1,1397.92 1217.1,1503.61 1172.1,1548.61 1172.1,1613.1 1244.9,1685.9 1460.48,1685.9 1567.69,1578.69 1571.45,1578.69 1574.9,1575.24 U1.3@1615.46,1575.24
DM_B: J1.5 U1.6 | length 859.7
  Top Layer w4.1: J1.5@1036,1382 988.99,1334.99 988.99,1287.63 1014.56,1262.05 1052.7,1262.05 1072.65,1282 1171.7,1282 1410.19,1520.49 1572.82,1520.49 1577.11,1516.2 U1.6@1615.46,1516.2
DM_C: J1.2 U1.11 | length 855.1
  Top Layer w4.1: J1.2@1036,1142 1079.89,1185.89 1079.89,1225.89 1103.5,1249.5 1258.5,1249.5 1291,1282 1291,1347 1389.85,1445.85 1396,1445.85 1401,1440.85 1401,1407 1416,1392 1451,1392 1461,1402 1461,1422 1485.47,1446.47 1544.31,1446.47 1569.53,1421.25 1583.56,1421.25 1587.01,1417.8 U1.11@1615.46,1417.8
DM_D: J1.9 U1.14 | length 847.9
  Top Layer w4.1: J1.9@1136,1182 1156,1162 1176,1162 1186,1152 1186,1052 1196,1042 1281,1042 1291,1052 1291,1147 1307.1,1163.1 1307.1,1227.4 1376,1296.3 1376,1337 1402.05,1363.05 1572.82,1363.05 1577.11,1358.76 U1.14@1615.46,1358.76
DP_A: J1.11 U1.2 | length 856.9
  Top Layer w4.1: J1.11@1136,1422 1136,1392 1141,1387 1164.9,1387 1206,1428.1 1206,1499.01 1161,1544.01 1161,1617.7 1240.3,1697 1465.08,1697 1567.16,1594.92 U1.2@1615.46,1594.92
DP_B: J1.4 U1.5 | length 849.8
  Top Layer w4.1: J1.4@1036,1302 1071,1337 1081,1337 1091,1327 1091,1317 1114.9,1293.1 1167.1,1293.1 1405.59,1531.59 1430.87,1531.59 1434.97,1535.69 1434.97,1597.9 1439.07,1602 1447.27,1602 1451.37,1597.9 1451.37,1535.69 1455.47,1531.59 1572.82,1531.59 1577.11,1535.88 U1.5@1615.46,1535.88
DP_C: J1.3 U1.10 | length 847.8
  Top Layer w4.1: J1.3@1036,1222 1060.3,1222 1098.9,1260.6 1253.9,1260.6 1279.9,1286.6 1279.9,1296.7 1275.8,1300.8 1255.1,1300.8 1251,1304.9 1251,1313.1 1255.1,1317.2 1275.8,1317.2 1279.9,1321.3 1279.9,1351.6 1385.25,1456.95 1400.6,1456.95 1412.1,1445.45 1412.1,1411.6 1420.6,1403.1 1446.4,1403.1 1449.9,1406.6 1449.9,1426.6 1480.87,1457.57 1548.91,1457.57 1569,1437.48 U1.10@1615.46,1437.48
DP_D: J1.8 U1.13 | length 855.2
  Top Layer w4.1: J1.8@1136,1102 1088.99,1149.01 1088.99,1196.22 1117.32,1224.55 1163.45,1224.55 1178.55,1209.45 1178.55,1179.45 1206.4,1151.6 1279.9,1151.6 1296,1167.7 1296,1232 1364.9,1300.9 1364.9,1341.6 1397.45,1374.15 1572.82,1374.15 1577.11,1378.44 U1.13@1615.46,1378.44
ERTH_GND: C19.2 C115.2 J1.13 J1.14 M203.1 R154.1 R352.1 | length 2257.7
  Top Layer w20: R154.1@169.62,1782 v1@201,1782 ; 238.48,944.5 J1.13@311,944.5 ; 238.48,1579.5 J1.14@311,1579.5 ; 311,871.98 J1.13@311,944.5 ; 311,1017.02 J1.13@311,944.5 ; 311,1506.98 J1.14@311,1579.5 ; 311,1652.02 J1.14@311,1579.5 ; v1@396,1707 426,1707 450.29,1731.29 C19.2@450.29,1752 ; v1@396,1752 C19.2@450.29,1752 ; v1@396,1802 436,1802 450.29,1787.71 C19.2@450.29,1752 ; v1@406,587 446,587 460.29,601.29 C115.2@460.29,637 ; v1@406,637 C115.2@460.29,637 ; v1@406,687 441,687 460.29,667.71 C115.2@460.29,637 ; v1@476,527 R352.1@507.38,527
  Mid-Layer 1 w20: 240.48,944.5 J1.13@311,944.5 ; 240.48,1579.5 J1.14@311,1579.5 ; 311,873.98 J1.13@311,944.5 ; 311,1015.02 J1.13@311,944.5 ; 311,1508.98 J1.14@311,1579.5 ; 311,1650.02 J1.14@311,1579.5
  Mid-Layer 2 w20: 240.48,944.5 J1.13@311,944.5 ; 240.48,1579.5 J1.14@311,1579.5 ; 311,873.98 J1.13@311,944.5 ; 311,1015.02 J1.13@311,944.5 ; 311,1508.98 J1.14@311,1579.5 ; 311,1650.02 J1.14@311,1579.5
  Bottom Layer w20: 238.48,944.5 J1.13@311,944.5 ; 238.48,1579.5 J1.14@311,1579.5 ; 311,871.98 J1.13@311,944.5 ; 311,1017.02 J1.13@311,944.5 ; 311,1506.98 J1.14@311,1579.5 ; 311,1652.02 J1.14@311,1579.5
  other v1: 163,46 418,176 428,311 328,456 478,526 248,541 408,586 408,636 343,651 218,666 408,686 288,756 448,806 123,921 253,1116 158,1231 393,1241 148,1386 323,1391 178,1626 418,1641 343,1701 398,1706 398,1751 278,1776 203,1781 398,1801
EXT_REF_CLK: R78.1 R98.1 | length 50
  Top Layer w5.4: R98.1@1951,987 R78.1@2001,987
EXT_RESET_N: J11.8 R35.2 R50.2 | length 6032.2
  Top Layer w5.4: R35.2@1721,1837 1681,1837 1656,1862 1558,1862 1538,1882 1536,1882 1536,1907 1466,1977 1466,2132 1408.7,2189.3 625.7,2189.3 556,2259 556,2597 646,2687 2183.34,2687 2197.14,2700.8 2234.86,2700.8 2248.66,2687 3552,2687 3661,2578 3661,2302 3546,2187 v1@3526,2187
  Bottom Layer w5.4: J11.8@3318.55,1967.58 3318.55,1939.45 3346,1912 3359.94,1898.06 3492.06,1898.06 3546,1952 3546,2017 3476,2087 3476,2157 3506,2187 v1@3526,2187
  other v1: 1683,1836 3346,1911 3528,2186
